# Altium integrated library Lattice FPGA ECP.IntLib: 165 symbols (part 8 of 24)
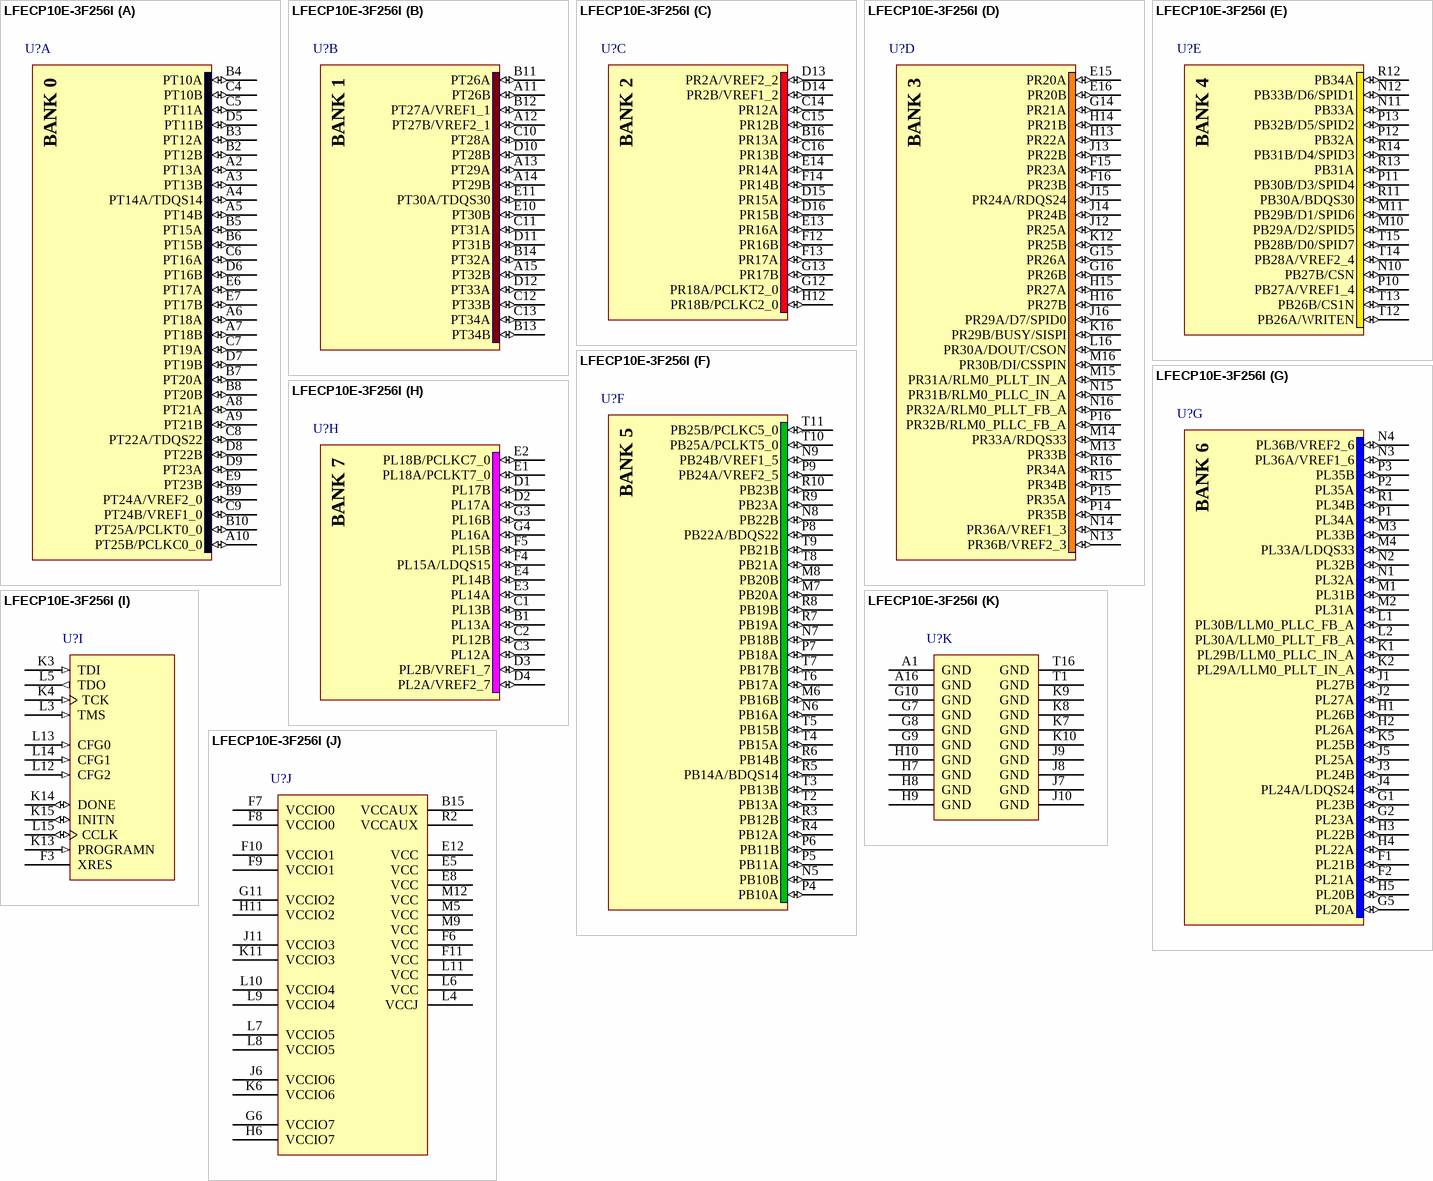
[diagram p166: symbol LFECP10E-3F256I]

## LFECP10E-3F256I
designator U?
ECP 1.2V FPGA, 192 I/Os, 4 PLLs, 10.2K LUTs, 5 sysDSP Blocks, 20 18x18 Multipliers, 256-Pin fpBGA, Speed Grade 3, Industrial Temperature Grade
footprint fpBGA256 (BGA, 256-Leads, Body 17x17mm, Pitch 1mm)
3D model ECP10E-fpBGA256 (256-Ball Fine Pitch Ball Grid Array (fpBGA256))
part A pins: A2 PT13A (io), A3 PT13B (io), A4 PT14A/TDQS14 (io), A5 PT14B (io), A6 PT18A (io), A7 PT18B (io), A8 PT21A (io), A9 PT21B (io), A10 PT25B/PCLKC0_0 (io), B2 PT12B (io), B3 PT12A (io), B4 PT10A (io), B5 PT15A (io), B6 PT15B (io), B7 PT20A (io), B8 PT20B (io), B9 PT24A/VREF2_0 (io), B10 PT25A/PCLKT0_0 (io), C4 PT10B (io), C5 PT11A (io), C6 PT16A (io), C7 PT19A (io), C8 PT22A/TDQS22 (io), C9 PT24B/VREF1_0 (io), D5 PT11B (io), D6 PT16B (io), D7 PT19B (io), D8 PT22B (io), D9 PT23A (io), E6 PT17A (io), E7 PT17B (io), E9 PT23B (io)
part B pins: A11 PT26B (io), A12 PT27B/VREF2_1 (io), A13 PT29A (io), A14 PT29B (io), A15 PT32B (io), B11 PT26A (io), B12 PT27A/VREF1_1 (io), B13 PT34B (io), B14 PT32A (io), C10 PT28A (io), C11 PT31A (io), C12 PT33B (io), C13 PT34A (io), D10 PT28B (io), D11 PT31B (io), D12 PT33A (io), E10 PT30B (io), E11 PT30A/TDQS30 (io)
part C pins: B16 PR13A (io), C14 PR12A (io), C15 PR12B (io), C16 PR13B (io), D13 PR2A/VREF2_2 (io), D14 PR2B/VREF1_2 (io), D15 PR15A (io), D16 PR15B (io), E13 PR16A (io), E14 PR14A (io), F12 PR16B (io), F13 PR17A (io), F14 PR14B (io), G12 PR18A/PCLKT2_0 (io), G13 PR17B (io), H12 PR18B/PCLKC2_0 (io)
part D pins: E15 PR20A (io), E16 PR20B (io), F15 PR23A (io), F16 PR23B (io), G14 PR21A (io), G15 PR26A (io), G16 PR26B (io), H13 PR22A (io), H14 PR21B (io), H15 PR27A (io), H16 PR27B (io), J12 PR25A (io), J13 PR22B (io), J14 PR24B (io), J15 PR24A/RDQS24 (io), J16 PR29A/D7/SPID0 (io), K12 PR25B (io), K16 PR29B/BUSY/SISPI (io), L16 PR30A/DOUT/CSON (io), M13 PR33B (io), M14 PR33A/RDQS33 (io), M15 PR31A/RLM0_PLLT_IN_A (io), M16 PR30B/DI/CSSPIN (io), N13 PR36B/VREF2_3 (io), N14 PR36A/VREF1_3 (io), N15 PR31B/RLM0_PLLC_IN_A (io), N16 PR32A/RLM0_PLLT_FB_A (io), P14 PR35B (io), P15 PR35A (io), P16 PR32B/RLM0_PLLC_FB_A (io), R15 PR34B (io), R16 PR34A (io)
part E pins: M10 PB29A/D2/SPID5 (io), M11 PB29B/D1/SPID6 (io), N10 PB27B/CSN (io), N11 PB33A (io), N12 PB33B/D6/SPID1 (io), P10 PB27A/VREF1_4 (io), P11 PB30B/D3/SPID4 (io), P12 PB32A (io), P13 PB32B/D5/SPID2 (io), R11 PB30A/BDQS30 (io), R12 PB34A (io), R13 PB31A (io), R14 PB31B/D4/SPID3 (io), T12 PB26A/WRITEN (io), T13 PB26B/CS1N (io), T14 PB28A/VREF2_4 (io), T15 PB28B/D0/SPID7 (io)
part F pins: M6 PB16B (io), M7 PB20A (io), M8 PB20B (io), N5 PB10B (io), N6 PB16A (io), N7 PB18B (io), N8 PB22B (io), N9 PB24B/VREF1_5 (io), P4 PB10A (io), P5 PB11A (io), P6 PB11B (io), P7 PB18A (io), P8 PB22A/BDQS22 (io), P9 PB24A/VREF2_5 (io), R3 PB12B (io), R4 PB12A (io), R5 PB14A/BDQS14 (io), R6 PB14B (io), R7 PB19A (io), R8 PB19B (io), R9 PB23A (io), R10 PB23B (io), T2 PB13A (io), T3 PB13B (io), T4 PB15A (io), T5 PB15B (io), T6 PB17A (io), T7 PB17B (io), T8 PB21A (io), T9 PB21B (io), T10 PB25A/PCLKT5_0 (io), T11 PB25B/PCLKC5_0 (io)
part G pins: F1 PL21B (io), F2 PL21A (io), G1 PL23B (io), G2 PL23A (io), G5 PL20A (io), H1 PL26B (io), H2 PL26A (io), H3 PL22B (io), H4 PL22A (io), H5 PL20B (io), J1 PL27B (io), J2 PL27A (io), J3 PL24B (io), J4 PL24A/LDQS24 (io), J5 PL25A (io), K1 PL29B/LLM0_PLLC_IN_A (io), K2 PL29A/LLM0_PLLT_IN_A (io), K5 PL25B (io), L1 PL30B/LLM0_PLLC_FB_A (io), L2 PL30A/LLM0_PLLT_FB_A (io), M1 PL31B (io), M2 PL31A (io), M3 PL33B (io), M4 PL33A/LDQS33 (io), N1 PL32A (io), N2 PL32B (io), N3 PL36A/VREF1_6 (io), N4 PL36B/VREF2_6 (io), P1 PL34A (io), P2 PL35A (io), P3 PL35B (io), R1 PL34B (io)
part H pins: B1 PL13A (io), C1 PL13B (io), C2 PL12B (io), C3 PL12A (io), D1 PL17B (io), D2 PL17A (io), D3 PL2B/VREF1_7 (io), D4 PL2A/VREF2_7 (io), E1 PL18A/PCLKT7_0 (io), E2 PL18B/PCLKC7_0 (io), E3 PL14A (io), E4 PL14B (io), F4 PL15A/LDQS15 (io), F5 PL15B (io), G3 PL16B (io), G4 PL16A (io)
part I pins: F3 XRES, K3 TDI (in), K4 TCK (in), K13 PROGRAMN (in), K14 DONE (io), K15 INITN (io), L3 TMS (in), L5 TDO (out), L12 CFG2 (in), L13 CFG0 (in), L14 CFG1 (in), L15 CCLK (io)
part J pins: B15 VCCAUX (power), E5 VCC (power), E8 VCC (power), E12 VCC (power), F6 VCC (power), F7 VCCIO0 (power), F8 VCCIO0 (power), F9 VCCIO1 (power), F10 VCCIO1 (power), F11 VCC (power), G6 VCCIO7 (power), G11 VCCIO2 (power), H6 VCCIO7 (power), H11 VCCIO2 (power), J6 VCCIO6 (power), J11 VCCIO3 (power), K6 VCCIO6 (power), K11 VCCIO3 (power), L4 VCCJ (power), L6 VCC (power), L7 VCCIO5 (power), L8 VCCIO5 (power), L9 VCCIO4 (power), L10 VCCIO4 (power), L11 VCC (power), M5 VCC (power), M9 VCC (power), M12 VCC (power), R2 VCCAUX (power)
part K pins: A1 GND (power), A16 GND (power), G7 GND (power), G8 GND (power), G9 GND (power), G10 GND (power), H7 GND (power), H8 GND (power), H9 GND (power), H10 GND (power), J7 GND (power), J8 GND (power), J9 GND (power), J10 GND (power), K7 GND (power), K8 GND (power), K9 GND (power), K10 GND (power), T1 GND (power), T16 GND (power)

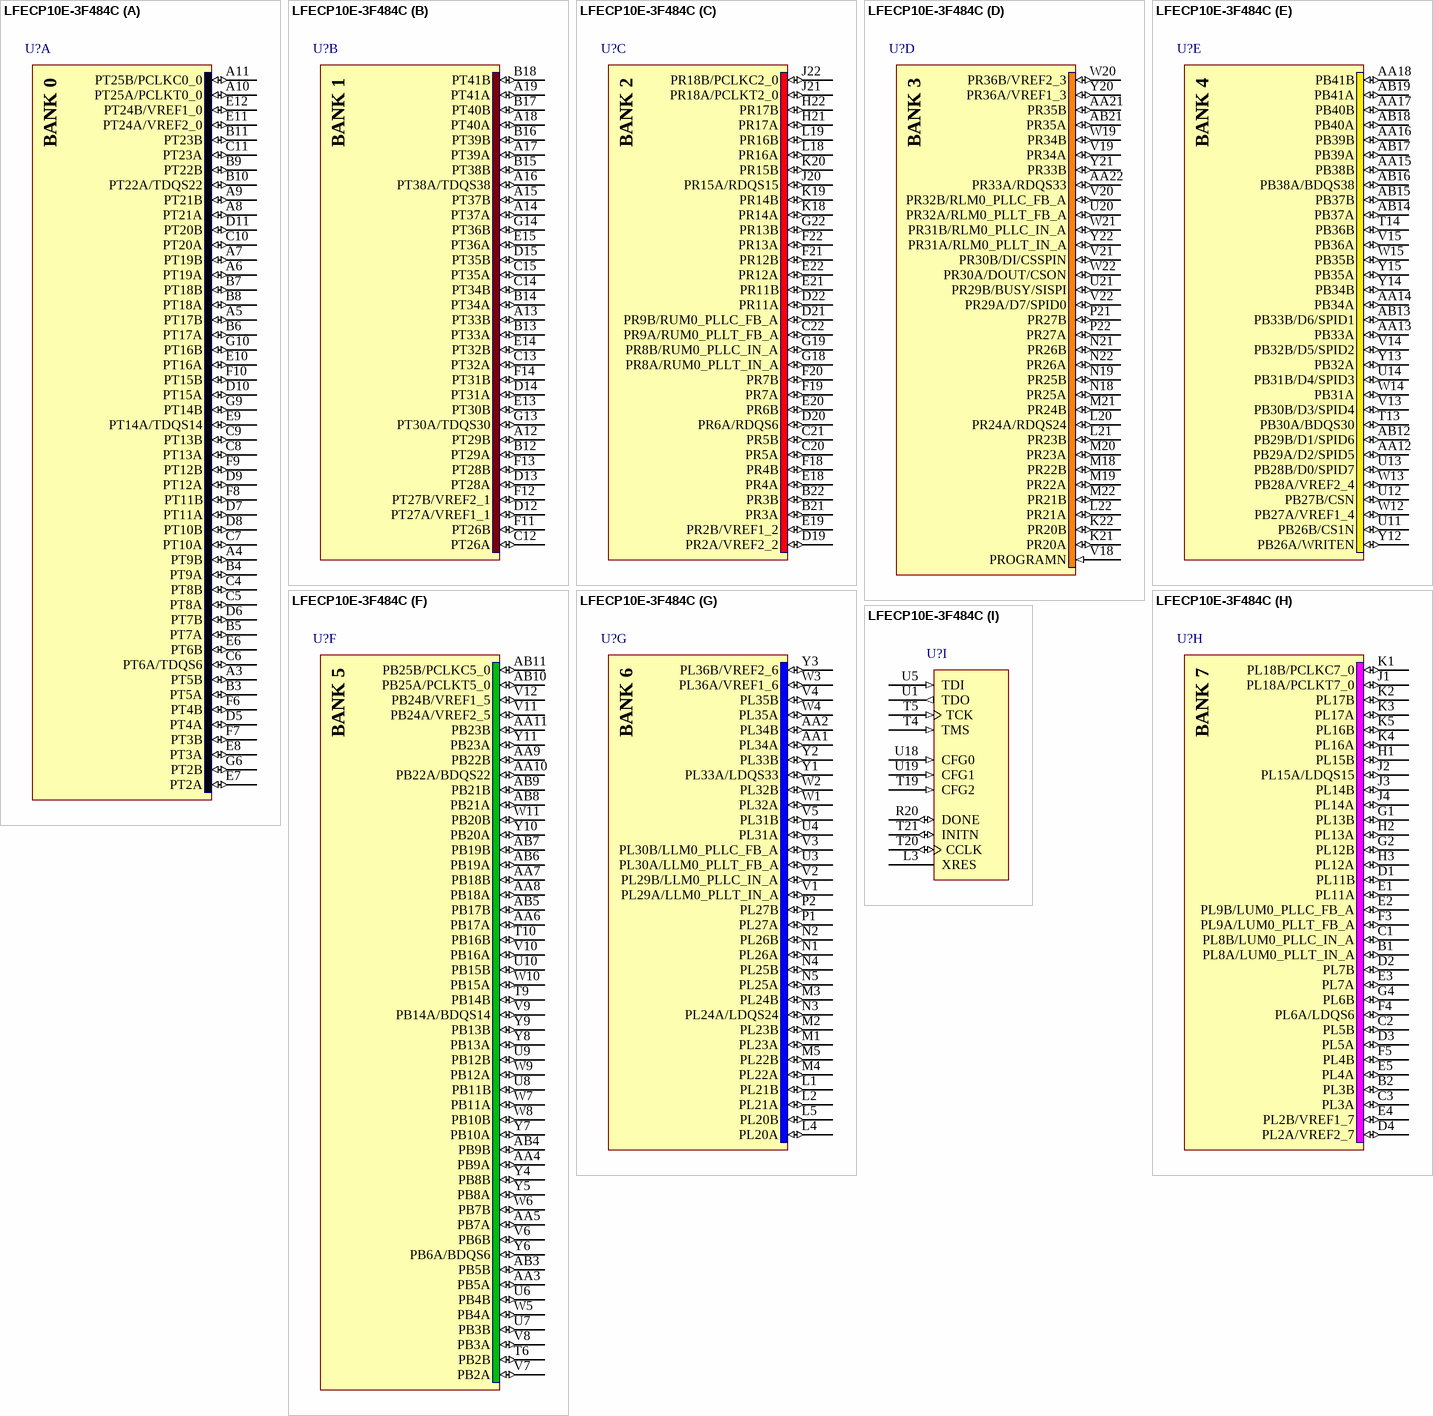
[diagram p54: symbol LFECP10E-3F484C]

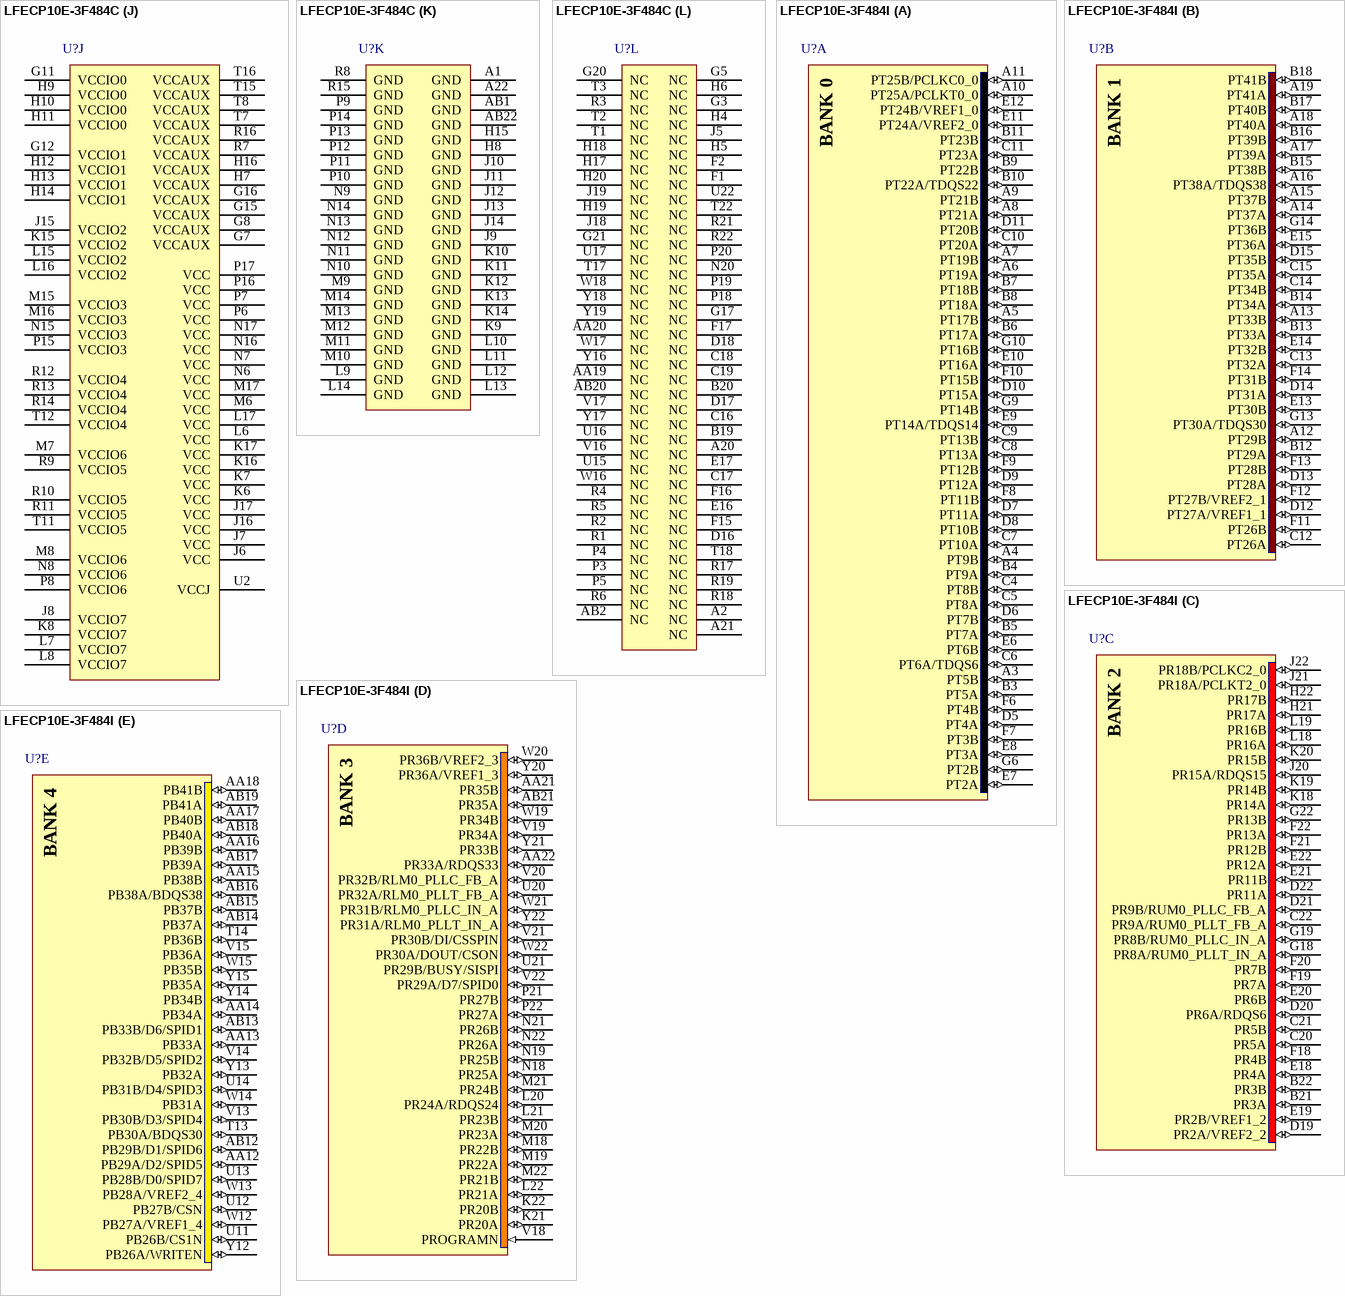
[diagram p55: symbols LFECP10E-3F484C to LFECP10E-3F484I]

## LFECP10E-3F484C
designator U?
ECP 1.2V FPGA, 288 I/Os, 4 PLLs, 10.2K LUTs, 5 sysDSP Blocks, 20 18x18 Multipliers, 484-Pin fpBGA, Speed Grade 3, Commercial Temperature Grade
footprint fpBGA484 (BGA, 484-Leads, Body 23x23mm, Pitch 1mm)
3D model ECP10E-fpBGA484 (484-Ball Fine Pitch Ball Grid Array (fpBGA484))
part A pins: A3 PT5B (io), A4 PT9B (io), A5 PT17B (io), A6 PT19A (io), A7 PT19B (io), A8 PT21A (io), A9 PT21B (io), A10 PT25A/PCLKT0_0 (io), A11 PT25B/PCLKC0_0 (io), B3 PT5A (io), B4 PT9A (io), B5 PT7A (io), B6 PT17A (io), B7 PT18B (io), B8 PT18A (io), B9 PT22B (io), B10 PT22A/TDQS22 (io), B11 PT23B (io), C4 PT8B (io), C5 PT8A (io), C6 PT6A/TDQS6 (io), C7 PT10A (io), C8 PT13A (io), C9 PT13B (io), C10 PT20A (io), C11 PT23A (io), D5 PT4A (io), D6 PT7B (io), D7 PT11A (io), D8 PT10B (io), D9 PT12A (io), D10 PT15A (io), D11 PT20B (io), E6 PT6B (io), E7 PT2A (io), E8 PT3A (io), E9 PT14A/TDQS14 (io), E10 PT16A (io), E11 PT24A/VREF2_0 (io), E12 PT24B/VREF1_0 (io), F6 PT4B (io), F7 PT3B (io), F8 PT11B (io), F9 PT12B (io), F10 PT15B (io), G6 PT2B (io), G9 PT14B (io), G10 PT16B (io)
part B pins: A12 PT29B (io), A13 PT33B (io), A14 PT37A (io), A15 PT37B (io), A16 PT38A/TDQS38 (io), A17 PT39A (io), A18 PT40A (io), A19 PT41A (io), B12 PT29A (io), B13 PT33A (io), B14 PT34A (io), B15 PT38B (io), B16 PT39B (io), B17 PT40B (io), B18 PT41B (io), C12 PT26A (io), C13 PT32A (io), C14 PT34B (io), C15 PT35A (io), D12 PT27A/VREF1_1 (io), D13 PT28A (io), D14 PT31A (io), D15 PT35B (io), E13 PT30B (io), E14 PT32B (io), E15 PT36A (io), F11 PT26B (io), F12 PT27B/VREF2_1 (io), F13 PT28B (io), F14 PT31B (io), G13 PT30A/TDQS30 (io), G14 PT36B (io)
part C pins: B21 PR3A (io), B22 PR3B (io), C20 PR5A (io), C21 PR5B (io), C22 PR9A/RUM0_PLLT_FB_A (io), D19 PR2A/VREF2_2 (io), D20 PR6A/RDQS6 (io), D21 PR9B/RUM0_PLLC_FB_A (io), D22 PR11A (io), E18 PR4A (io), E19 PR2B/VREF1_2 (io), E20 PR6B (io), E21 PR11B (io), E22 PR12A (io), F18 PR4B (io), F19 PR7A (io), F20 PR7B (io), F21 PR12B (io), F22 PR13A (io), G18 PR8A/RUM0_PLLT_IN_A (io), G19 PR8B/RUM0_PLLC_IN_A (io), G22 PR13B (io), H21 PR17A (io), H22 PR17B (io), J20 PR15A/RDQS15 (io), J21 PR18A/PCLKT2_0 (io), J22 PR18B/PCLKC2_0 (io), K18 PR14A (io), K19 PR14B (io), K20 PR15B (io), L18 PR16A (io), L19 PR16B (io)
part D pins: AA21 PR35B (io), AA22 PR33A/RDQS33 (io), AB21 PR35A (io), K21 PR20A (io), K22 PR20B (io), L20 PR24A/RDQS24 (io), L21 PR23B (io), L22 PR21A (io), M18 PR22B (io), M19 PR22A (io), M20 PR23A (io), M21 PR24B (io), M22 PR21B (io), N18 PR25A (io), N19 PR25B (io), N21 PR26B (io), N22 PR26A (io), P21 PR27B (io), P22 PR27A (io), U20 PR32A/RLM0_PLLT_FB_A (io), U21 PR29B/BUSY/SISPI (io), V18 PROGRAMN (in), V19 PR34A (io), V20 PR32B/RLM0_PLLC_FB_A (io), V21 PR30B/DI/CSSPIN (io), V22 PR29A/D7/SPID0 (io), W19 PR34B (io), W20 PR36B/VREF2_3 (io), W21 PR31B/RLM0_PLLC_IN_A (io), W22 PR30A/DOUT/CSON (io), Y20 PR36A/VREF1_3 (io), Y21 PR33B (io), Y22 PR31A/RLM0_PLLT_IN_A (io)
part E pins: AA12 PB29A/D2/SPID5 (io), AA13 PB33A (io), AA14 PB34A (io), AA15 PB38B (io), AA16 PB39B (io), AA17 PB40B (io), AA18 PB41B (io), AB12 PB29B/D1/SPID6 (io), AB13 PB33B/D6/SPID1 (io), AB14 PB37A (io), AB15 PB37B (io), AB16 PB38A/BDQS38 (io), AB17 PB39A (io), AB18 PB40A (io), AB19 PB41A (io), T13 PB30A/BDQS30 (io), T14 PB36B (io), U11 PB26B/CS1N (io), U12 PB27B/CSN (io), U13 PB28B/D0/SPID7 (io), U14 PB31B/D4/SPID3 (io), V13 PB30B/D3/SPID4 (io), V14 PB32B/D5/SPID2 (io), V15 PB36A (io), W12 PB27A/VREF1_4 (io), W13 PB28A/VREF2_4 (io), W14 PB31A (io), W15 PB35B (io), Y12 PB26A/WRITEN (io), Y13 PB32A (io), Y14 PB34B (io), Y15 PB35A (io)
part F pins: AA3 PB5A (io), AA4 PB9A (io), AA5 PB7A (io), AA6 PB17A (io), AA7 PB18B (io), AA8 PB18A (io), AA9 PB22B (io), AA10 PB22A/BDQS22 (io), AA11 PB23B (io), AB3 PB5B (io), AB4 PB9B (io), AB5 PB17B (io), AB6 PB19A (io), AB7 PB19B (io), AB8 PB21A (io), AB9 PB21B (io), AB10 PB25A/PCLKT5_0 (io), AB11 PB25B/PCLKC5_0 (io), T6 PB2B (io), T9 PB14B (io), T10 PB16B (io), U6 PB4B (io), U7 PB3B (io), U8 PB11B (io), U9 PB12B (io), U10 PB15B (io), V6 PB6B (io), V7 PB2A (io), V8 PB3A (io), V9 PB14A/BDQS14 (io), V10 PB16A (io), V11 PB24A/VREF2_5 (io), V12 PB24B/VREF1_5 (io), W5 PB4A (io), W6 PB7B (io), W7 PB11A (io), W8 PB10B (io), W9 PB12A (io), W10 PB15A (io), W11 PB20B (io), Y4 PB8B (io), Y5 PB8A (io), Y6 PB6A/BDQS6 (io), Y7 PB10A (io), Y8 PB13A (io), Y9 PB13B (io), Y10 PB20A (io), Y11 PB23A (io)
part G pins: AA1 PL34A (io), AA2 PL34B (io), L1 PL21B (io), L2 PL21A (io), L4 PL20A (io), L5 PL20B (io), M1 PL23A (io), M2 PL23B (io), M3 PL24B (io), M4 PL22A (io), M5 PL22B (io), N1 PL26A (io), N2 PL26B (io), N3 PL24A/LDQS24 (io), N4 PL25B (io), N5 PL25A (io), P1 PL27A (io), P2 PL27B (io), U3 PL30A/LLM0_PLLT_FB_A (io), U4 PL31A (io), V1 PL29A/LLM0_PLLT_IN_A (io), V2 PL29B/LLM0_PLLC_IN_A (io), V3 PL30B/LLM0_PLLC_FB_A (io), V4 PL35B (io), V5 PL31B (io), W1 PL32A (io), W2 PL32B (io), W3 PL36A/VREF1_6 (io), W4 PL35A (io), Y1 PL33A/LDQS33 (io), Y2 PL33B (io), Y3 PL36B/VREF2_6 (io)
part H pins: B1 PL8A/LUM0_PLLT_IN_A (io), B2 PL3B (io), C1 PL8B/LUM0_PLLC_IN_A (io), C2 PL5B (io), C3 PL3A (io), D1 PL11B (io), D2 PL7B (io), D3 PL5A (io), D4 PL2A/VREF2_7 (io), E1 PL11A (io), E2 PL9B/LUM0_PLLC_FB_A (io), E3 PL7A (io), E4 PL2B/VREF1_7 (io), E5 PL4A (io), F3 PL9A/LUM0_PLLT_FB_A (io), F4 PL6A/LDQS6 (io), F5 PL4B (io), G1 PL13B (io), G2 PL12B (io), G4 PL6B (io), H1 PL15B (io), H2 PL13A (io), H3 PL12A (io), J1 PL18A/PCLKT7_0 (io), J2 PL15A/LDQS15 (io), J3 PL14B (io), J4 PL14A (io), K1 PL18B/PCLKC7_0 (io), K2 PL17B (io), K3 PL17A (io), K4 PL16A (io), K5 PL16B (io)
part I pins: L3 XRES, R20 DONE (io), T4 TMS (in), T5 TCK (in), T19 CFG2 (in), T20 CCLK (io), T21 INITN (io), U1 TDO (out), U5 TDI (in), U18 CFG0 (in), U19 CFG1 (in)
part J pins: G7 VCCAUX (power), G8 VCCAUX (power), G11 VCCIO0 (power), G12 VCCIO1 (power), G15 VCCAUX (power), G16 VCCAUX (power), H7 VCCAUX (power), H9 VCCIO0 (power), H10 VCCIO0 (power), H11 VCCIO0 (power), H12 VCCIO1 (power), H13 VCCIO1 (power), H14 VCCIO1 (power), H16 VCCAUX (power), J6 VCC (power), J7 VCC (power), J8 VCCIO7 (power), J15 VCCIO2 (power), J16 VCC (power), J17 VCC (power), K6 VCC (power), K7 VCC (power), K8 VCCIO7 (power), K15 VCCIO2 (power), K16 VCC (power), K17 VCC (power), L6 VCC (power), L7 VCCIO7 (power), L8 VCCIO7 (power), L15 VCCIO2 (power), L16 VCCIO2 (power), L17 VCC (power), M6 VCC (power), M7 VCCIO6 (power), M8 VCCIO6 (power), M15 VCCIO3 (power), M16 VCCIO3 (power), M17 VCC (power), N6 VCC (power), N7 VCC (power), N8 VCCIO6 (power), N15 VCCIO3 (power), N16 VCC (power), N17 VCC (power), P6 VCC (power), P7 VCC (power), P8 VCCIO6 (power), P15 VCCIO3 (power), P16 VCC (power), P17 VCC (power), R7 VCCAUX (power), R9 VCCIO5 (power), R10 VCCIO5 (power), R11 VCCIO5 (power), R12 VCCIO4 (power), R13 VCCIO4 (power), R14 VCCIO4 (power), R16 VCCAUX (power), T7 VCCAUX (power), T8 VCCAUX (power), T11 VCCIO5 (power), T12 VCCIO4 (power), T15 VCCAUX (power), T16 VCCAUX (power), U2 VCCJ (power)
part K pins: A1 GND (power), A22 GND (power), AB1 GND (power), AB22 GND (power), H8 GND (power), H15 GND (power), J9 GND (power), J10 GND (power), J11 GND (power), J12 GND (power), J13 GND (power), J14 GND (power), K9 GND (power), K10 GND (power), K11 GND (power), K12 GND (power), K13 GND (power), K14 GND (power), L9 GND (power), L10 GND (power), L11 GND (power), L12 GND (power), L13 GND (power), L14 GND (power), M9 GND (power), M10 GND (power), M11 GND (power), M12 GND (power), M13 GND (power), M14 GND (power), N9 GND (power), N10 GND (power), N11 GND (power), N12 GND (power), N13 GND (power), N14 GND (power), P9 GND (power), P10 GND (power), P11 GND (power), P12 GND (power), P13 GND (power), P14 GND (power), R8 GND (power), R15 GND (power)
part L pins: A2 NC, A20 NC, A21 NC, AA19 NC, AA20 NC, AB2 NC, AB20 NC, B19 NC, B20 NC, C16 NC, C17 NC, C18 NC, C19 NC, D16 NC, D17 NC, D18 NC, E16 NC, E17 NC, F1 NC, F2 NC, F15 NC, F16 NC, F17 NC, G3 NC, G5 NC, G17 NC, G20 NC, G21 NC, H4 NC, H5 NC, H6 NC, H17 NC, H18 NC, H19 NC, H20 NC, J5 NC, J18 NC, J19 NC, N20 NC, P3 NC, P4 NC, P5 NC, P18 NC, P19 NC, P20 NC, R1 NC, R2 NC, R3 NC, R4 NC, R5 NC, R6 NC, R17 NC, R18 NC, R19 NC, R21 NC, R22 NC, T1 NC, T2 NC, T3 NC, T17 NC, T18 NC, T22 NC, U15 NC, U16 NC, U17 NC, U22 NC, V16 NC, V17 NC, W16 NC, W17 NC, W18 NC, Y16 NC, Y17 NC, Y18 NC, Y19 NC

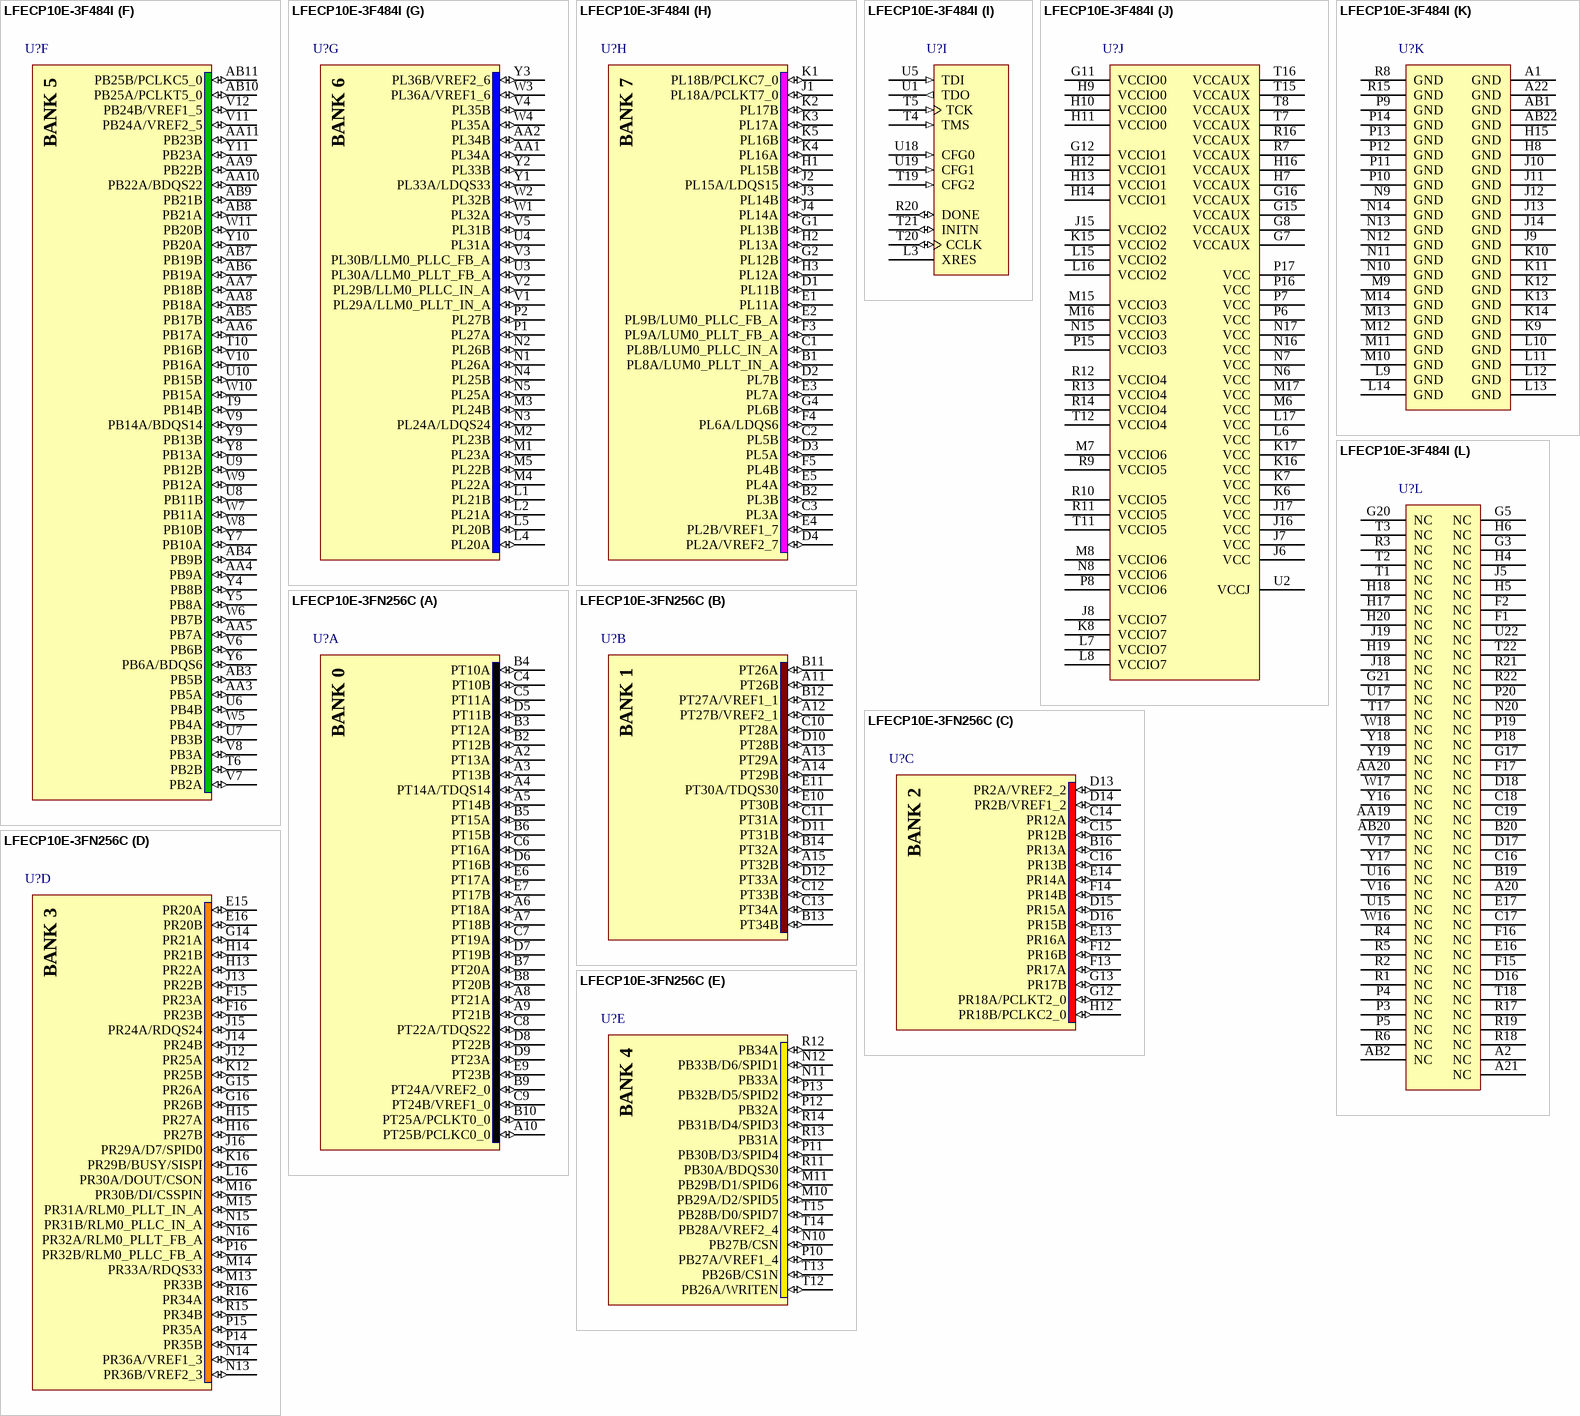
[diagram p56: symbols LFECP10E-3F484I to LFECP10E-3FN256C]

## LFECP10E-3F484I
designator U?
ECP 1.2V FPGA, 288 I/Os, 4 PLLs, 10.2K LUTs, 5 sysDSP Blocks, 20 18x18 Multipliers, 484-Pin fpBGA, Speed Grade 3, Industrial Temperature Grade
footprint fpBGA484 (BGA, 484-Leads, Body 23x23mm, Pitch 1mm)
3D model ECP10E-fpBGA484 (484-Ball Fine Pitch Ball Grid Array (fpBGA484))
part A pins: A3 PT5B (io), A4 PT9B (io), A5 PT17B (io), A6 PT19A (io), A7 PT19B (io), A8 PT21A (io), A9 PT21B (io), A10 PT25A/PCLKT0_0 (io), A11 PT25B/PCLKC0_0 (io), B3 PT5A (io), B4 PT9A (io), B5 PT7A (io), B6 PT17A (io), B7 PT18B (io), B8 PT18A (io), B9 PT22B (io), B10 PT22A/TDQS22 (io), B11 PT23B (io), C4 PT8B (io), C5 PT8A (io), C6 PT6A/TDQS6 (io), C7 PT10A (io), C8 PT13A (io), C9 PT13B (io), C10 PT20A (io), C11 PT23A (io), D5 PT4A (io), D6 PT7B (io), D7 PT11A (io), D8 PT10B (io), D9 PT12A (io), D10 PT15A (io), D11 PT20B (io), E6 PT6B (io), E7 PT2A (io), E8 PT3A (io), E9 PT14A/TDQS14 (io), E10 PT16A (io), E11 PT24A/VREF2_0 (io), E12 PT24B/VREF1_0 (io), F6 PT4B (io), F7 PT3B (io), F8 PT11B (io), F9 PT12B (io), F10 PT15B (io), G6 PT2B (io), G9 PT14B (io), G10 PT16B (io)
part B pins: A12 PT29B (io), A13 PT33B (io), A14 PT37A (io), A15 PT37B (io), A16 PT38A/TDQS38 (io), A17 PT39A (io), A18 PT40A (io), A19 PT41A (io), B12 PT29A (io), B13 PT33A (io), B14 PT34A (io), B15 PT38B (io), B16 PT39B (io), B17 PT40B (io), B18 PT41B (io), C12 PT26A (io), C13 PT32A (io), C14 PT34B (io), C15 PT35A (io), D12 PT27A/VREF1_1 (io), D13 PT28A (io), D14 PT31A (io), D15 PT35B (io), E13 PT30B (io), E14 PT32B (io), E15 PT36A (io), F11 PT26B (io), F12 PT27B/VREF2_1 (io), F13 PT28B (io), F14 PT31B (io), G13 PT30A/TDQS30 (io), G14 PT36B (io)
part C pins: B21 PR3A (io), B22 PR3B (io), C20 PR5A (io), C21 PR5B (io), C22 PR9A/RUM0_PLLT_FB_A (io), D19 PR2A/VREF2_2 (io), D20 PR6A/RDQS6 (io), D21 PR9B/RUM0_PLLC_FB_A (io), D22 PR11A (io), E18 PR4A (io), E19 PR2B/VREF1_2 (io), E20 PR6B (io), E21 PR11B (io), E22 PR12A (io), F18 PR4B (io), F19 PR7A (io), F20 PR7B (io), F21 PR12B (io), F22 PR13A (io), G18 PR8A/RUM0_PLLT_IN_A (io), G19 PR8B/RUM0_PLLC_IN_A (io), G22 PR13B (io), H21 PR17A (io), H22 PR17B (io), J20 PR15A/RDQS15 (io), J21 PR18A/PCLKT2_0 (io), J22 PR18B/PCLKC2_0 (io), K18 PR14A (io), K19 PR14B (io), K20 PR15B (io), L18 PR16A (io), L19 PR16B (io)
part D pins: AA21 PR35B (io), AA22 PR33A/RDQS33 (io), AB21 PR35A (io), K21 PR20A (io), K22 PR20B (io), L20 PR24A/RDQS24 (io), L21 PR23B (io), L22 PR21A (io), M18 PR22B (io), M19 PR22A (io), M20 PR23A (io), M21 PR24B (io), M22 PR21B (io), N18 PR25A (io), N19 PR25B (io), N21 PR26B (io), N22 PR26A (io), P21 PR27B (io), P22 PR27A (io), U20 PR32A/RLM0_PLLT_FB_A (io), U21 PR29B/BUSY/SISPI (io), V18 PROGRAMN (in), V19 PR34A (io), V20 PR32B/RLM0_PLLC_FB_A (io), V21 PR30B/DI/CSSPIN (io), V22 PR29A/D7/SPID0 (io), W19 PR34B (io), W20 PR36B/VREF2_3 (io), W21 PR31B/RLM0_PLLC_IN_A (io), W22 PR30A/DOUT/CSON (io), Y20 PR36A/VREF1_3 (io), Y21 PR33B (io), Y22 PR31A/RLM0_PLLT_IN_A (io)
part E pins: AA12 PB29A/D2/SPID5 (io), AA13 PB33A (io), AA14 PB34A (io), AA15 PB38B (io), AA16 PB39B (io), AA17 PB40B (io), AA18 PB41B (io), AB12 PB29B/D1/SPID6 (io), AB13 PB33B/D6/SPID1 (io), AB14 PB37A (io), AB15 PB37B (io), AB16 PB38A/BDQS38 (io), AB17 PB39A (io), AB18 PB40A (io), AB19 PB41A (io), T13 PB30A/BDQS30 (io), T14 PB36B (io), U11 PB26B/CS1N (io), U12 PB27B/CSN (io), U13 PB28B/D0/SPID7 (io), U14 PB31B/D4/SPID3 (io), V13 PB30B/D3/SPID4 (io), V14 PB32B/D5/SPID2 (io), V15 PB36A (io), W12 PB27A/VREF1_4 (io), W13 PB28A/VREF2_4 (io), W14 PB31A (io), W15 PB35B (io), Y12 PB26A/WRITEN (io), Y13 PB32A (io), Y14 PB34B (io), Y15 PB35A (io)
part F pins: AA3 PB5A (io), AA4 PB9A (io), AA5 PB7A (io), AA6 PB17A (io), AA7 PB18B (io), AA8 PB18A (io), AA9 PB22B (io), AA10 PB22A/BDQS22 (io), AA11 PB23B (io), AB3 PB5B (io), AB4 PB9B (io), AB5 PB17B (io), AB6 PB19A (io), AB7 PB19B (io), AB8 PB21A (io), AB9 PB21B (io), AB10 PB25A/PCLKT5_0 (io), AB11 PB25B/PCLKC5_0 (io), T6 PB2B (io), T9 PB14B (io), T10 PB16B (io), U6 PB4B (io), U7 PB3B (io), U8 PB11B (io), U9 PB12B (io), U10 PB15B (io), V6 PB6B (io), V7 PB2A (io), V8 PB3A (io), V9 PB14A/BDQS14 (io), V10 PB16A (io), V11 PB24A/VREF2_5 (io), V12 PB24B/VREF1_5 (io), W5 PB4A (io), W6 PB7B (io), W7 PB11A (io), W8 PB10B (io), W9 PB12A (io), W10 PB15A (io), W11 PB20B (io), Y4 PB8B (io), Y5 PB8A (io), Y6 PB6A/BDQS6 (io), Y7 PB10A (io), Y8 PB13A (io), Y9 PB13B (io), Y10 PB20A (io), Y11 PB23A (io)
part G pins: AA1 PL34A (io), AA2 PL34B (io), L1 PL21B (io), L2 PL21A (io), L4 PL20A (io), L5 PL20B (io), M1 PL23A (io), M2 PL23B (io), M3 PL24B (io), M4 PL22A (io), M5 PL22B (io), N1 PL26A (io), N2 PL26B (io), N3 PL24A/LDQS24 (io), N4 PL25B (io), N5 PL25A (io), P1 PL27A (io), P2 PL27B (io), U3 PL30A/LLM0_PLLT_FB_A (io), U4 PL31A (io), V1 PL29A/LLM0_PLLT_IN_A (io), V2 PL29B/LLM0_PLLC_IN_A (io), V3 PL30B/LLM0_PLLC_FB_A (io), V4 PL35B (io), V5 PL31B (io), W1 PL32A (io), W2 PL32B (io), W3 PL36A/VREF1_6 (io), W4 PL35A (io), Y1 PL33A/LDQS33 (io), Y2 PL33B (io), Y3 PL36B/VREF2_6 (io)
part H pins: B1 PL8A/LUM0_PLLT_IN_A (io), B2 PL3B (io), C1 PL8B/LUM0_PLLC_IN_A (io), C2 PL5B (io), C3 PL3A (io), D1 PL11B (io), D2 PL7B (io), D3 PL5A (io), D4 PL2A/VREF2_7 (io), E1 PL11A (io), E2 PL9B/LUM0_PLLC_FB_A (io), E3 PL7A (io), E4 PL2B/VREF1_7 (io), E5 PL4A (io), F3 PL9A/LUM0_PLLT_FB_A (io), F4 PL6A/LDQS6 (io), F5 PL4B (io), G1 PL13B (io), G2 PL12B (io), G4 PL6B (io), H1 PL15B (io), H2 PL13A (io), H3 PL12A (io), J1 PL18A/PCLKT7_0 (io), J2 PL15A/LDQS15 (io), J3 PL14B (io), J4 PL14A (io), K1 PL18B/PCLKC7_0 (io), K2 PL17B (io), K3 PL17A (io), K4 PL16A (io), K5 PL16B (io)
part I pins: L3 XRES, R20 DONE (io), T4 TMS (in), T5 TCK (in), T19 CFG2 (in), T20 CCLK (io), T21 INITN (io), U1 TDO (out), U5 TDI (in), U18 CFG0 (in), U19 CFG1 (in)
part J pins: G7 VCCAUX (power), G8 VCCAUX (power), G11 VCCIO0 (power), G12 VCCIO1 (power), G15 VCCAUX (power), G16 VCCAUX (power), H7 VCCAUX (power), H9 VCCIO0 (power), H10 VCCIO0 (power), H11 VCCIO0 (power), H12 VCCIO1 (power), H13 VCCIO1 (power), H14 VCCIO1 (power), H16 VCCAUX (power), J6 VCC (power), J7 VCC (power), J8 VCCIO7 (power), J15 VCCIO2 (power), J16 VCC (power), J17 VCC (power), K6 VCC (power), K7 VCC (power), K8 VCCIO7 (power), K15 VCCIO2 (power), K16 VCC (power), K17 VCC (power), L6 VCC (power), L7 VCCIO7 (power), L8 VCCIO7 (power), L15 VCCIO2 (power), L16 VCCIO2 (power), L17 VCC (power), M6 VCC (power), M7 VCCIO6 (power), M8 VCCIO6 (power), M15 VCCIO3 (power), M16 VCCIO3 (power), M17 VCC (power), N6 VCC (power), N7 VCC (power), N8 VCCIO6 (power), N15 VCCIO3 (power), N16 VCC (power), N17 VCC (power), P6 VCC (power), P7 VCC (power), P8 VCCIO6 (power), P15 VCCIO3 (power), P16 VCC (power), P17 VCC (power), R7 VCCAUX (power), R9 VCCIO5 (power), R10 VCCIO5 (power), R11 VCCIO5 (power), R12 VCCIO4 (power), R13 VCCIO4 (power), R14 VCCIO4 (power), R16 VCCAUX (power), T7 VCCAUX (power), T8 VCCAUX (power), T11 VCCIO5 (power), T12 VCCIO4 (power), T15 VCCAUX (power), T16 VCCAUX (power), U2 VCCJ (power)
part K pins: A1 GND (power), A22 GND (power), AB1 GND (power), AB22 GND (power), H8 GND (power), H15 GND (power), J9 GND (power), J10 GND (power), J11 GND (power), J12 GND (power), J13 GND (power), J14 GND (power), K9 GND (power), K10 GND (power), K11 GND (power), K12 GND (power), K13 GND (power), K14 GND (power), L9 GND (power), L10 GND (power), L11 GND (power), L12 GND (power), L13 GND (power), L14 GND (power), M9 GND (power), M10 GND (power), M11 GND (power), M12 GND (power), M13 GND (power), M14 GND (power), N9 GND (power), N10 GND (power), N11 GND (power), N12 GND (power), N13 GND (power), N14 GND (power), P9 GND (power), P10 GND (power), P11 GND (power), P12 GND (power), P13 GND (power), P14 GND (power), R8 GND (power), R15 GND (power)
part L pins: A2 NC, A20 NC, A21 NC, AA19 NC, AA20 NC, AB2 NC, AB20 NC, B19 NC, B20 NC, C16 NC, C17 NC, C18 NC, C19 NC, D16 NC, D17 NC, D18 NC, E16 NC, E17 NC, F1 NC, F2 NC, F15 NC, F16 NC, F17 NC, G3 NC, G5 NC, G17 NC, G20 NC, G21 NC, H4 NC, H5 NC, H6 NC, H17 NC, H18 NC, H19 NC, H20 NC, J5 NC, J18 NC, J19 NC, N20 NC, P3 NC, P4 NC, P5 NC, P18 NC, P19 NC, P20 NC, R1 NC, R2 NC, R3 NC, R4 NC, R5 NC, R6 NC, R17 NC, R18 NC, R19 NC, R21 NC, R22 NC, T1 NC, T2 NC, T3 NC, T17 NC, T18 NC, T22 NC, U15 NC, U16 NC, U17 NC, U22 NC, V16 NC, V17 NC, W16 NC, W17 NC, W18 NC, Y16 NC, Y17 NC, Y18 NC, Y19 NC

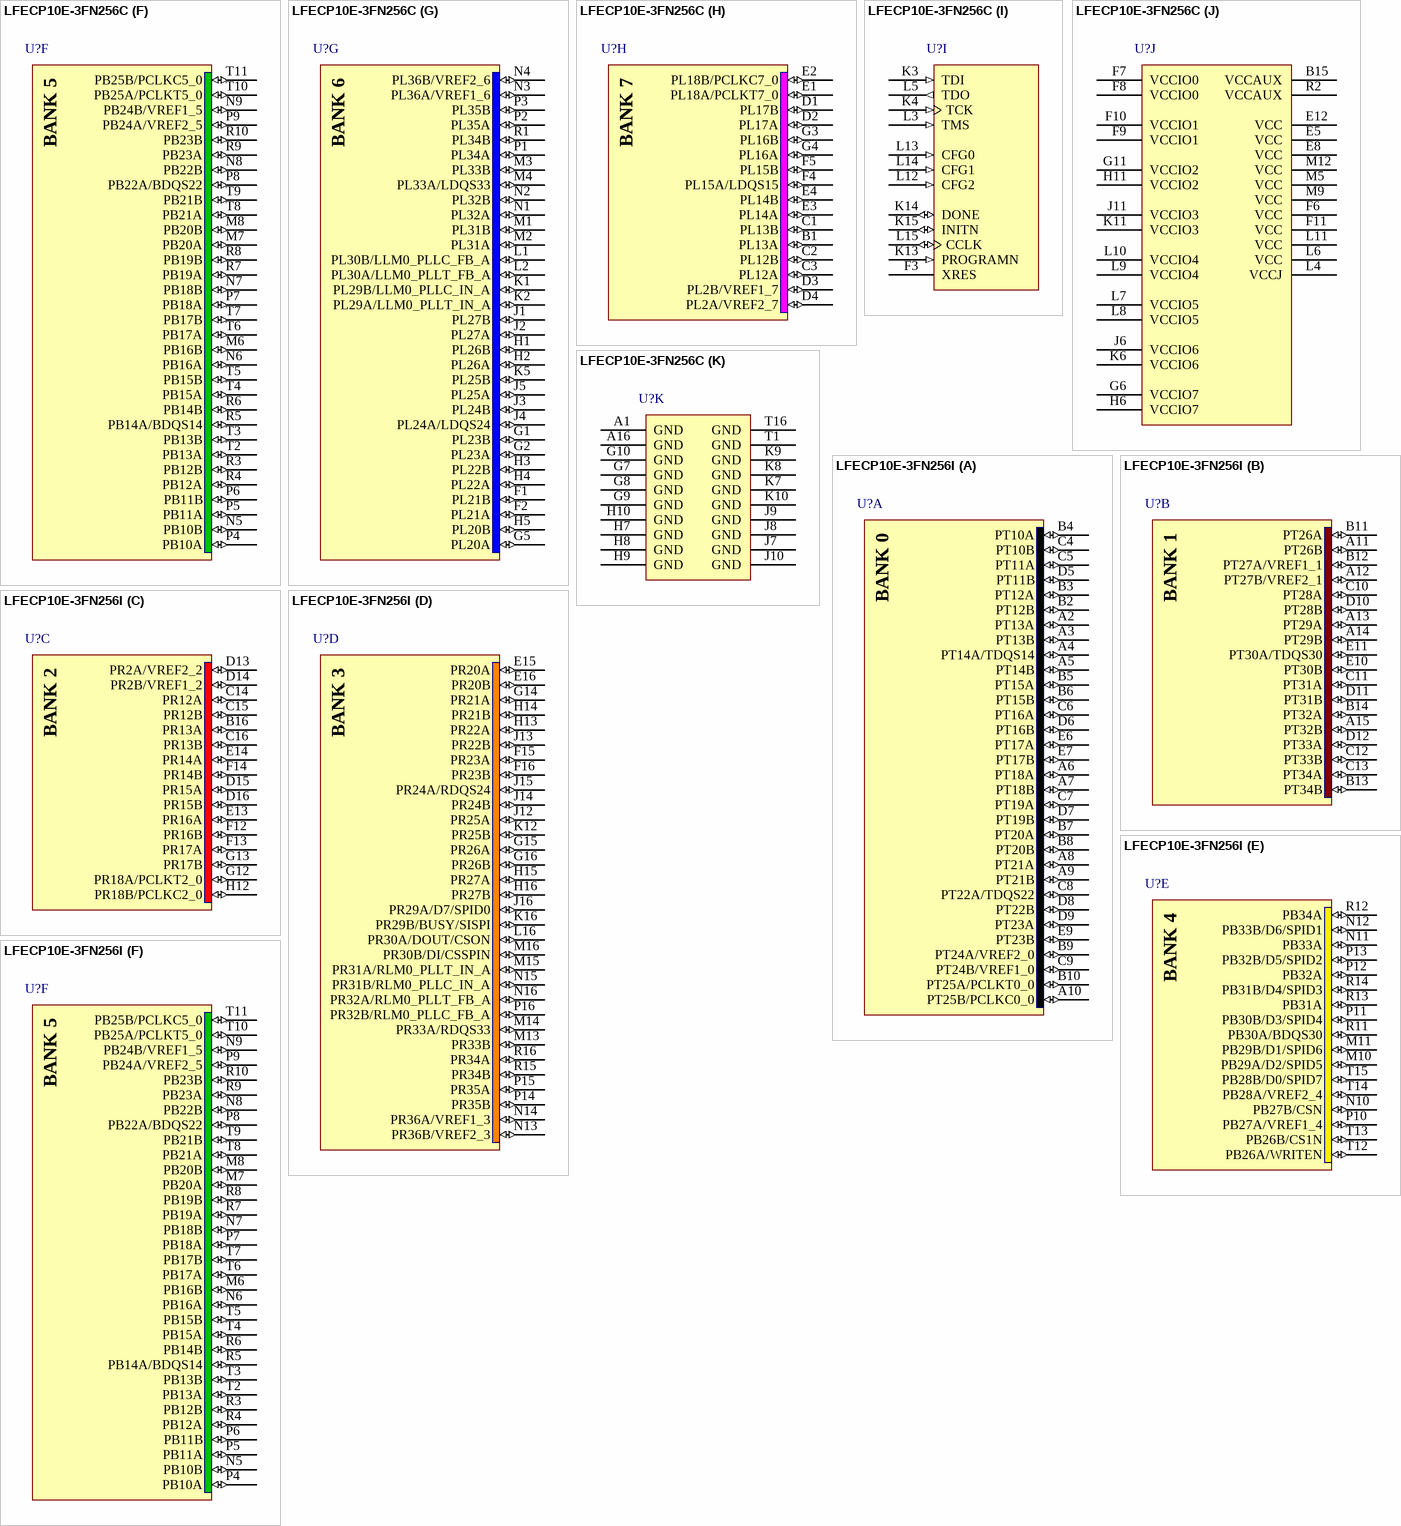
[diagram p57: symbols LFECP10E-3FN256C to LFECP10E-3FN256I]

## LFECP10E-3FN256C
designator U?
ECP 1.2V FPGA, 195 I/Os, 4 PLLs, 10.2K LUTs, 5 sysDSP Blocks, 20 18x18 Multipliers, 256-Pin fpBGA, Pb-Free, Speed Grade 3, Commercial Temperature Grade
footprint fpBGA256 (BGA, 256-Leads, Body 17x17mm, Pitch 1mm)
3D model ECP10E-fpBGA256 (256-Ball Fine Pitch Ball Grid Array (fpBGA256))
part A pins: A2 PT13A (io), A3 PT13B (io), A4 PT14A/TDQS14 (io), A5 PT14B (io), A6 PT18A (io), A7 PT18B (io), A8 PT21A (io), A9 PT21B (io), A10 PT25B/PCLKC0_0 (io), B2 PT12B (io), B3 PT12A (io), B4 PT10A (io), B5 PT15A (io), B6 PT15B (io), B7 PT20A (io), B8 PT20B (io), B9 PT24A/VREF2_0 (io), B10 PT25A/PCLKT0_0 (io), C4 PT10B (io), C5 PT11A (io), C6 PT16A (io), C7 PT19A (io), C8 PT22A/TDQS22 (io), C9 PT24B/VREF1_0 (io), D5 PT11B (io), D6 PT16B (io), D7 PT19B (io), D8 PT22B (io), D9 PT23A (io), E6 PT17A (io), E7 PT17B (io), E9 PT23B (io)
part B pins: A11 PT26B (io), A12 PT27B/VREF2_1 (io), A13 PT29A (io), A14 PT29B (io), A15 PT32B (io), B11 PT26A (io), B12 PT27A/VREF1_1 (io), B13 PT34B (io), B14 PT32A (io), C10 PT28A (io), C11 PT31A (io), C12 PT33B (io), C13 PT34A (io), D10 PT28B (io), D11 PT31B (io), D12 PT33A (io), E10 PT30B (io), E11 PT30A/TDQS30 (io)
part C pins: B16 PR13A (io), C14 PR12A (io), C15 PR12B (io), C16 PR13B (io), D13 PR2A/VREF2_2 (io), D14 PR2B/VREF1_2 (io), D15 PR15A (io), D16 PR15B (io), E13 PR16A (io), E14 PR14A (io), F12 PR16B (io), F13 PR17A (io), F14 PR14B (io), G12 PR18A/PCLKT2_0 (io), G13 PR17B (io), H12 PR18B/PCLKC2_0 (io)
part D pins: E15 PR20A (io), E16 PR20B (io), F15 PR23A (io), F16 PR23B (io), G14 PR21A (io), G15 PR26A (io), G16 PR26B (io), H13 PR22A (io), H14 PR21B (io), H15 PR27A (io), H16 PR27B (io), J12 PR25A (io), J13 PR22B (io), J14 PR24B (io), J15 PR24A/RDQS24 (io), J16 PR29A/D7/SPID0 (io), K12 PR25B (io), K16 PR29B/BUSY/SISPI (io), L16 PR30A/DOUT/CSON (io), M13 PR33B (io), M14 PR33A/RDQS33 (io), M15 PR31A/RLM0_PLLT_IN_A (io), M16 PR30B/DI/CSSPIN (io), N13 PR36B/VREF2_3 (io), N14 PR36A/VREF1_3 (io), N15 PR31B/RLM0_PLLC_IN_A (io), N16 PR32A/RLM0_PLLT_FB_A (io), P14 PR35B (io), P15 PR35A (io), P16 PR32B/RLM0_PLLC_FB_A (io), R15 PR34B (io), R16 PR34A (io)
part E pins: M10 PB29A/D2/SPID5 (io), M11 PB29B/D1/SPID6 (io), N10 PB27B/CSN (io), N11 PB33A (io), N12 PB33B/D6/SPID1 (io), P10 PB27A/VREF1_4 (io), P11 PB30B/D3/SPID4 (io), P12 PB32A (io), P13 PB32B/D5/SPID2 (io), R11 PB30A/BDQS30 (io), R12 PB34A (io), R13 PB31A (io), R14 PB31B/D4/SPID3 (io), T12 PB26A/WRITEN (io), T13 PB26B/CS1N (io), T14 PB28A/VREF2_4 (io), T15 PB28B/D0/SPID7 (io)
part F pins: M6 PB16B (io), M7 PB20A (io), M8 PB20B (io), N5 PB10B (io), N6 PB16A (io), N7 PB18B (io), N8 PB22B (io), N9 PB24B/VREF1_5 (io), P4 PB10A (io), P5 PB11A (io), P6 PB11B (io), P7 PB18A (io), P8 PB22A/BDQS22 (io), P9 PB24A/VREF2_5 (io), R3 PB12B (io), R4 PB12A (io), R5 PB14A/BDQS14 (io), R6 PB14B (io), R7 PB19A (io), R8 PB19B (io), R9 PB23A (io), R10 PB23B (io), T2 PB13A (io), T3 PB13B (io), T4 PB15A (io), T5 PB15B (io), T6 PB17A (io), T7 PB17B (io), T8 PB21A (io), T9 PB21B (io), T10 PB25A/PCLKT5_0 (io), T11 PB25B/PCLKC5_0 (io)
part G pins: F1 PL21B (io), F2 PL21A (io), G1 PL23B (io), G2 PL23A (io), G5 PL20A (io), H1 PL26B (io), H2 PL26A (io), H3 PL22B (io), H4 PL22A (io), H5 PL20B (io), J1 PL27B (io), J2 PL27A (io), J3 PL24B (io), J4 PL24A/LDQS24 (io), J5 PL25A (io), K1 PL29B/LLM0_PLLC_IN_A (io), K2 PL29A/LLM0_PLLT_IN_A (io), K5 PL25B (io), L1 PL30B/LLM0_PLLC_FB_A (io), L2 PL30A/LLM0_PLLT_FB_A (io), M1 PL31B (io), M2 PL31A (io), M3 PL33B (io), M4 PL33A/LDQS33 (io), N1 PL32A (io), N2 PL32B (io), N3 PL36A/VREF1_6 (io), N4 PL36B/VREF2_6 (io), P1 PL34A (io), P2 PL35A (io), P3 PL35B (io), R1 PL34B (io)
part H pins: B1 PL13A (io), C1 PL13B (io), C2 PL12B (io), C3 PL12A (io), D1 PL17B (io), D2 PL17A (io), D3 PL2B/VREF1_7 (io), D4 PL2A/VREF2_7 (io), E1 PL18A/PCLKT7_0 (io), E2 PL18B/PCLKC7_0 (io), E3 PL14A (io), E4 PL14B (io), F4 PL15A/LDQS15 (io), F5 PL15B (io), G3 PL16B (io), G4 PL16A (io)
part I pins: F3 XRES, K3 TDI (in), K4 TCK (in), K13 PROGRAMN (in), K14 DONE (io), K15 INITN (io), L3 TMS (in), L5 TDO (out), L12 CFG2 (in), L13 CFG0 (in), L14 CFG1 (in), L15 CCLK (io)
part J pins: B15 VCCAUX (power), E5 VCC (power), E8 VCC (power), E12 VCC (power), F6 VCC (power), F7 VCCIO0 (power), F8 VCCIO0 (power), F9 VCCIO1 (power), F10 VCCIO1 (power), F11 VCC (power), G6 VCCIO7 (power), G11 VCCIO2 (power), H6 VCCIO7 (power), H11 VCCIO2 (power), J6 VCCIO6 (power), J11 VCCIO3 (power), K6 VCCIO6 (power), K11 VCCIO3 (power), L4 VCCJ (power), L6 VCC (power), L7 VCCIO5 (power), L8 VCCIO5 (power), L9 VCCIO4 (power), L10 VCCIO4 (power), L11 VCC (power), M5 VCC (power), M9 VCC (power), M12 VCC (power), R2 VCCAUX (power)
part K pins: A1 GND (power), A16 GND (power), G7 GND (power), G8 GND (power), G9 GND (power), G10 GND (power), H7 GND (power), H8 GND (power), H9 GND (power), H10 GND (power), J7 GND (power), J8 GND (power), J9 GND (power), J10 GND (power), K7 GND (power), K8 GND (power), K9 GND (power), K10 GND (power), T1 GND (power), T16 GND (power)

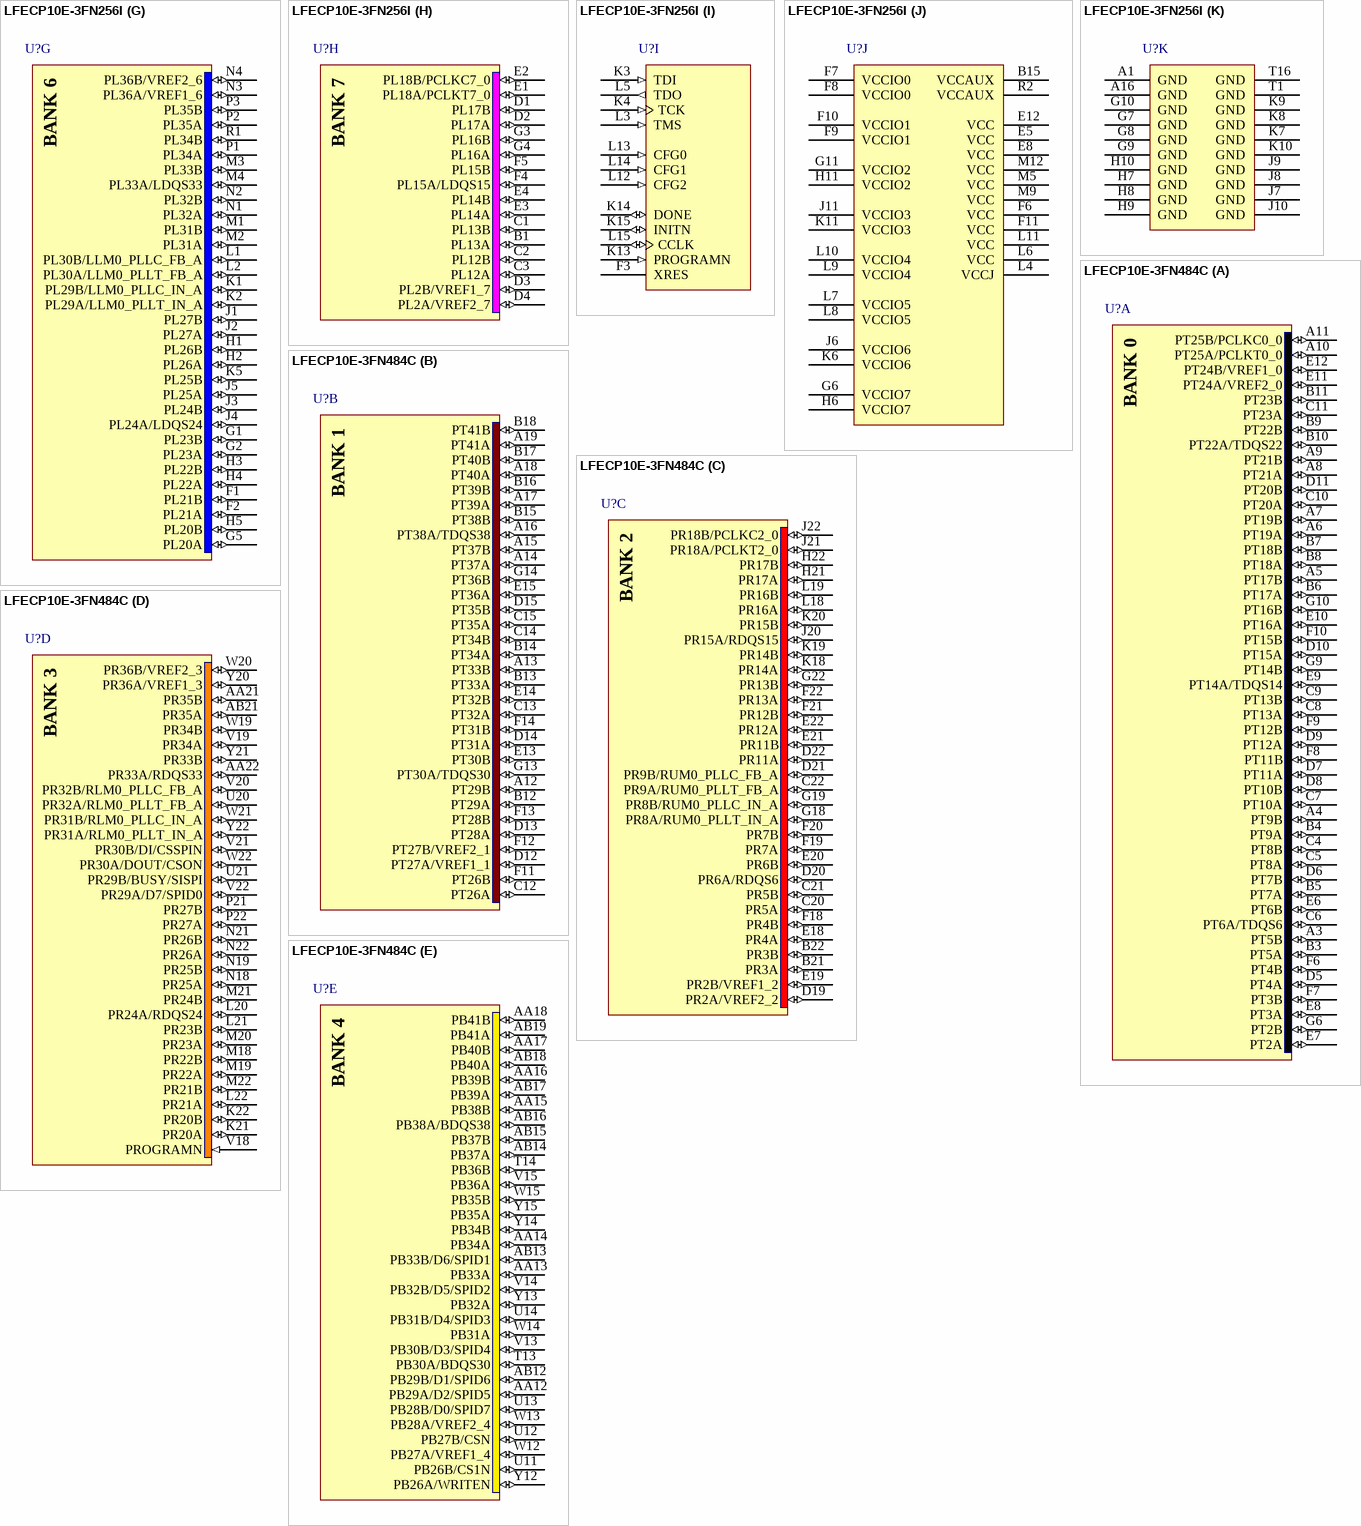
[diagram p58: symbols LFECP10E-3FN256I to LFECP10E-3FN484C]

## LFECP10E-3FN256I
designator U?
ECP 1.2V FPGA, 195 I/Os, 4 PLLs, 10.2K LUTs, 5 sysDSP Blocks, 20 18x18 Multipliers, 256-Pin fpBGA, Pb-Free, Speed Grade 3, Industrial Temperature Grade
footprint fpBGA256 (BGA, 256-Leads, Body 17x17mm, Pitch 1mm)
3D model ECP10E-fpBGA256 (256-Ball Fine Pitch Ball Grid Array (fpBGA256))
part A pins: A2 PT13A (io), A3 PT13B (io), A4 PT14A/TDQS14 (io), A5 PT14B (io), A6 PT18A (io), A7 PT18B (io), A8 PT21A (io), A9 PT21B (io), A10 PT25B/PCLKC0_0 (io), B2 PT12B (io), B3 PT12A (io), B4 PT10A (io), B5 PT15A (io), B6 PT15B (io), B7 PT20A (io), B8 PT20B (io), B9 PT24A/VREF2_0 (io), B10 PT25A/PCLKT0_0 (io), C4 PT10B (io), C5 PT11A (io), C6 PT16A (io), C7 PT19A (io), C8 PT22A/TDQS22 (io), C9 PT24B/VREF1_0 (io), D5 PT11B (io), D6 PT16B (io), D7 PT19B (io), D8 PT22B (io), D9 PT23A (io), E6 PT17A (io), E7 PT17B (io), E9 PT23B (io)
part B pins: A11 PT26B (io), A12 PT27B/VREF2_1 (io), A13 PT29A (io), A14 PT29B (io), A15 PT32B (io), B11 PT26A (io), B12 PT27A/VREF1_1 (io), B13 PT34B (io), B14 PT32A (io), C10 PT28A (io), C11 PT31A (io), C12 PT33B (io), C13 PT34A (io), D10 PT28B (io), D11 PT31B (io), D12 PT33A (io), E10 PT30B (io), E11 PT30A/TDQS30 (io)
part C pins: B16 PR13A (io), C14 PR12A (io), C15 PR12B (io), C16 PR13B (io), D13 PR2A/VREF2_2 (io), D14 PR2B/VREF1_2 (io), D15 PR15A (io), D16 PR15B (io), E13 PR16A (io), E14 PR14A (io), F12 PR16B (io), F13 PR17A (io), F14 PR14B (io), G12 PR18A/PCLKT2_0 (io), G13 PR17B (io), H12 PR18B/PCLKC2_0 (io)
part D pins: E15 PR20A (io), E16 PR20B (io), F15 PR23A (io), F16 PR23B (io), G14 PR21A (io), G15 PR26A (io), G16 PR26B (io), H13 PR22A (io), H14 PR21B (io), H15 PR27A (io), H16 PR27B (io), J12 PR25A (io), J13 PR22B (io), J14 PR24B (io), J15 PR24A/RDQS24 (io), J16 PR29A/D7/SPID0 (io), K12 PR25B (io), K16 PR29B/BUSY/SISPI (io), L16 PR30A/DOUT/CSON (io), M13 PR33B (io), M14 PR33A/RDQS33 (io), M15 PR31A/RLM0_PLLT_IN_A (io), M16 PR30B/DI/CSSPIN (io), N13 PR36B/VREF2_3 (io), N14 PR36A/VREF1_3 (io), N15 PR31B/RLM0_PLLC_IN_A (io), N16 PR32A/RLM0_PLLT_FB_A (io), P14 PR35B (io), P15 PR35A (io), P16 PR32B/RLM0_PLLC_FB_A (io), R15 PR34B (io), R16 PR34A (io)
part E pins: M10 PB29A/D2/SPID5 (io), M11 PB29B/D1/SPID6 (io), N10 PB27B/CSN (io), N11 PB33A (io), N12 PB33B/D6/SPID1 (io), P10 PB27A/VREF1_4 (io), P11 PB30B/D3/SPID4 (io), P12 PB32A (io), P13 PB32B/D5/SPID2 (io), R11 PB30A/BDQS30 (io), R12 PB34A (io), R13 PB31A (io), R14 PB31B/D4/SPID3 (io), T12 PB26A/WRITEN (io), T13 PB26B/CS1N (io), T14 PB28A/VREF2_4 (io), T15 PB28B/D0/SPID7 (io)
part F pins: M6 PB16B (io), M7 PB20A (io), M8 PB20B (io), N5 PB10B (io), N6 PB16A (io), N7 PB18B (io), N8 PB22B (io), N9 PB24B/VREF1_5 (io), P4 PB10A (io), P5 PB11A (io), P6 PB11B (io), P7 PB18A (io), P8 PB22A/BDQS22 (io), P9 PB24A/VREF2_5 (io), R3 PB12B (io), R4 PB12A (io), R5 PB14A/BDQS14 (io), R6 PB14B (io), R7 PB19A (io), R8 PB19B (io), R9 PB23A (io), R10 PB23B (io), T2 PB13A (io), T3 PB13B (io), T4 PB15A (io), T5 PB15B (io), T6 PB17A (io), T7 PB17B (io), T8 PB21A (io), T9 PB21B (io), T10 PB25A/PCLKT5_0 (io), T11 PB25B/PCLKC5_0 (io)
part G pins: F1 PL21B (io), F2 PL21A (io), G1 PL23B (io), G2 PL23A (io), G5 PL20A (io), H1 PL26B (io), H2 PL26A (io), H3 PL22B (io), H4 PL22A (io), H5 PL20B (io), J1 PL27B (io), J2 PL27A (io), J3 PL24B (io), J4 PL24A/LDQS24 (io), J5 PL25A (io), K1 PL29B/LLM0_PLLC_IN_A (io), K2 PL29A/LLM0_PLLT_IN_A (io), K5 PL25B (io), L1 PL30B/LLM0_PLLC_FB_A (io), L2 PL30A/LLM0_PLLT_FB_A (io), M1 PL31B (io), M2 PL31A (io), M3 PL33B (io), M4 PL33A/LDQS33 (io), N1 PL32A (io), N2 PL32B (io), N3 PL36A/VREF1_6 (io), N4 PL36B/VREF2_6 (io), P1 PL34A (io), P2 PL35A (io), P3 PL35B (io), R1 PL34B (io)
part H pins: B1 PL13A (io), C1 PL13B (io), C2 PL12B (io), C3 PL12A (io), D1 PL17B (io), D2 PL17A (io), D3 PL2B/VREF1_7 (io), D4 PL2A/VREF2_7 (io), E1 PL18A/PCLKT7_0 (io), E2 PL18B/PCLKC7_0 (io), E3 PL14A (io), E4 PL14B (io), F4 PL15A/LDQS15 (io), F5 PL15B (io), G3 PL16B (io), G4 PL16A (io)
part I pins: F3 XRES, K3 TDI (in), K4 TCK (in), K13 PROGRAMN (in), K14 DONE (io), K15 INITN (io), L3 TMS (in), L5 TDO (out), L12 CFG2 (in), L13 CFG0 (in), L14 CFG1 (in), L15 CCLK (io)
part J pins: B15 VCCAUX (power), E5 VCC (power), E8 VCC (power), E12 VCC (power), F6 VCC (power), F7 VCCIO0 (power), F8 VCCIO0 (power), F9 VCCIO1 (power), F10 VCCIO1 (power), F11 VCC (power), G6 VCCIO7 (power), G11 VCCIO2 (power), H6 VCCIO7 (power), H11 VCCIO2 (power), J6 VCCIO6 (power), J11 VCCIO3 (power), K6 VCCIO6 (power), K11 VCCIO3 (power), L4 VCCJ (power), L6 VCC (power), L7 VCCIO5 (power), L8 VCCIO5 (power), L9 VCCIO4 (power), L10 VCCIO4 (power), L11 VCC (power), M5 VCC (power), M9 VCC (power), M12 VCC (power), R2 VCCAUX (power)
part K pins: A1 GND (power), A16 GND (power), G7 GND (power), G8 GND (power), G9 GND (power), G10 GND (power), H7 GND (power), H8 GND (power), H9 GND (power), H10 GND (power), J7 GND (power), J8 GND (power), J9 GND (power), J10 GND (power), K7 GND (power), K8 GND (power), K9 GND (power), K10 GND (power), T1 GND (power), T16 GND (power)

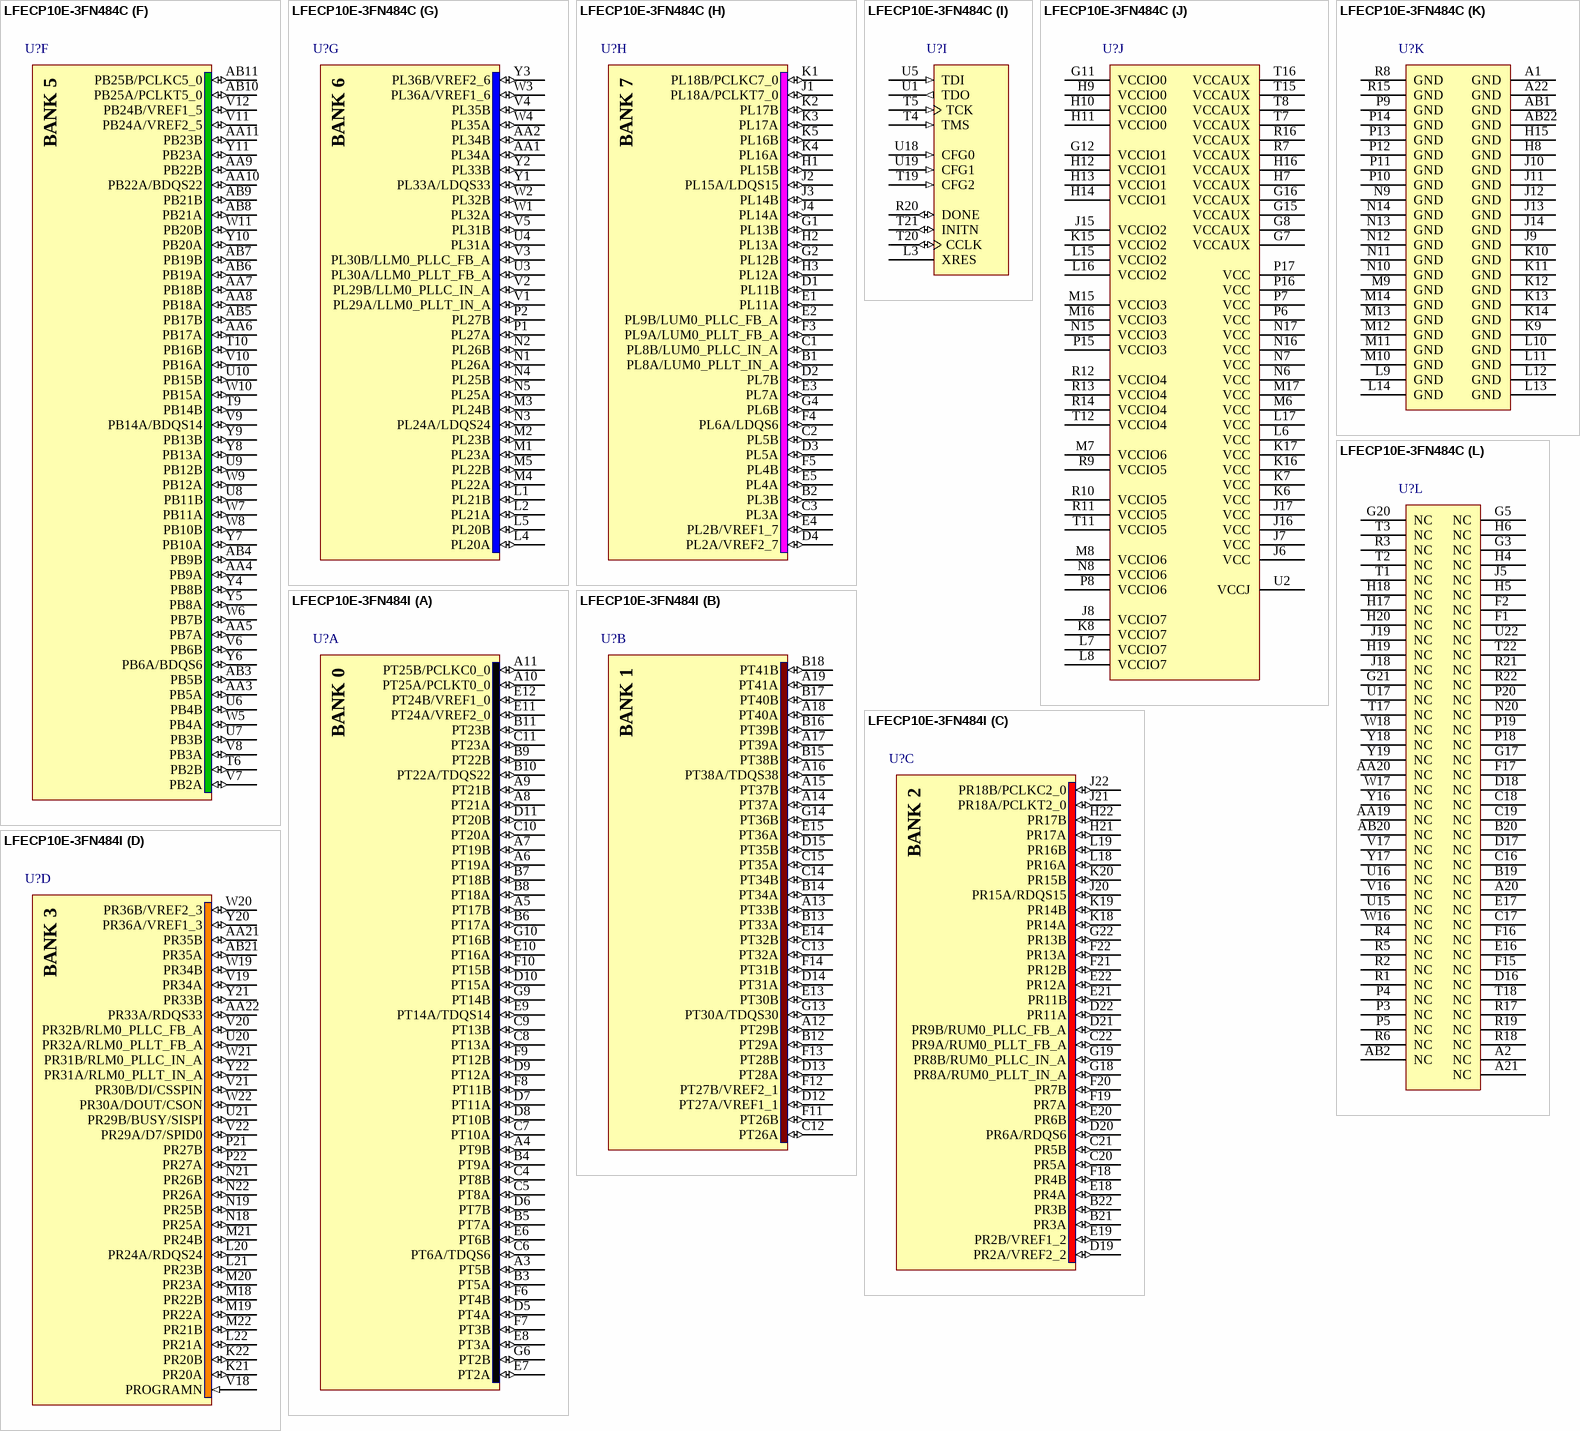
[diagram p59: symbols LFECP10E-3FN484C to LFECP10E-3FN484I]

## LFECP10E-3FN484C
designator U?
ECP 1.2V FPGA, 228 I/Os, 4 PLLs, 10.2K LUTs, 5 sysDSP Blocks, 20 18x18 Multipliers, 484-Pin fpBGA, Pb-Free, Speed Grade 3, Commercial Temperature Grade
footprint fpBGA484 (BGA, 484-Leads, Body 23x23mm, Pitch 1mm)
3D model ECP10E-fpBGA484 (484-Ball Fine Pitch Ball Grid Array (fpBGA484))
part A pins: A3 PT5B (io), A4 PT9B (io), A5 PT17B (io), A6 PT19A (io), A7 PT19B (io), A8 PT21A (io), A9 PT21B (io), A10 PT25A/PCLKT0_0 (io), A11 PT25B/PCLKC0_0 (io), B3 PT5A (io), B4 PT9A (io), B5 PT7A (io), B6 PT17A (io), B7 PT18B (io), B8 PT18A (io), B9 PT22B (io), B10 PT22A/TDQS22 (io), B11 PT23B (io), C4 PT8B (io), C5 PT8A (io), C6 PT6A/TDQS6 (io), C7 PT10A (io), C8 PT13A (io), C9 PT13B (io), C10 PT20A (io), C11 PT23A (io), D5 PT4A (io), D6 PT7B (io), D7 PT11A (io), D8 PT10B (io), D9 PT12A (io), D10 PT15A (io), D11 PT20B (io), E6 PT6B (io), E7 PT2A (io), E8 PT3A (io), E9 PT14A/TDQS14 (io), E10 PT16A (io), E11 PT24A/VREF2_0 (io), E12 PT24B/VREF1_0 (io), F6 PT4B (io), F7 PT3B (io), F8 PT11B (io), F9 PT12B (io), F10 PT15B (io), G6 PT2B (io), G9 PT14B (io), G10 PT16B (io)
part B pins: A12 PT29B (io), A13 PT33B (io), A14 PT37A (io), A15 PT37B (io), A16 PT38A/TDQS38 (io), A17 PT39A (io), A18 PT40A (io), A19 PT41A (io), B12 PT29A (io), B13 PT33A (io), B14 PT34A (io), B15 PT38B (io), B16 PT39B (io), B17 PT40B (io), B18 PT41B (io), C12 PT26A (io), C13 PT32A (io), C14 PT34B (io), C15 PT35A (io), D12 PT27A/VREF1_1 (io), D13 PT28A (io), D14 PT31A (io), D15 PT35B (io), E13 PT30B (io), E14 PT32B (io), E15 PT36A (io), F11 PT26B (io), F12 PT27B/VREF2_1 (io), F13 PT28B (io), F14 PT31B (io), G13 PT30A/TDQS30 (io), G14 PT36B (io)
part C pins: B21 PR3A (io), B22 PR3B (io), C20 PR5A (io), C21 PR5B (io), C22 PR9A/RUM0_PLLT_FB_A (io), D19 PR2A/VREF2_2 (io), D20 PR6A/RDQS6 (io), D21 PR9B/RUM0_PLLC_FB_A (io), D22 PR11A (io), E18 PR4A (io), E19 PR2B/VREF1_2 (io), E20 PR6B (io), E21 PR11B (io), E22 PR12A (io), F18 PR4B (io), F19 PR7A (io), F20 PR7B (io), F21 PR12B (io), F22 PR13A (io), G18 PR8A/RUM0_PLLT_IN_A (io), G19 PR8B/RUM0_PLLC_IN_A (io), G22 PR13B (io), H21 PR17A (io), H22 PR17B (io), J20 PR15A/RDQS15 (io), J21 PR18A/PCLKT2_0 (io), J22 PR18B/PCLKC2_0 (io), K18 PR14A (io), K19 PR14B (io), K20 PR15B (io), L18 PR16A (io), L19 PR16B (io)
part D pins: AA21 PR35B (io), AA22 PR33A/RDQS33 (io), AB21 PR35A (io), K21 PR20A (io), K22 PR20B (io), L20 PR24A/RDQS24 (io), L21 PR23B (io), L22 PR21A (io), M18 PR22B (io), M19 PR22A (io), M20 PR23A (io), M21 PR24B (io), M22 PR21B (io), N18 PR25A (io), N19 PR25B (io), N21 PR26B (io), N22 PR26A (io), P21 PR27B (io), P22 PR27A (io), U20 PR32A/RLM0_PLLT_FB_A (io), U21 PR29B/BUSY/SISPI (io), V18 PROGRAMN (in), V19 PR34A (io), V20 PR32B/RLM0_PLLC_FB_A (io), V21 PR30B/DI/CSSPIN (io), V22 PR29A/D7/SPID0 (io), W19 PR34B (io), W20 PR36B/VREF2_3 (io), W21 PR31B/RLM0_PLLC_IN_A (io), W22 PR30A/DOUT/CSON (io), Y20 PR36A/VREF1_3 (io), Y21 PR33B (io), Y22 PR31A/RLM0_PLLT_IN_A (io)
part E pins: AA12 PB29A/D2/SPID5 (io), AA13 PB33A (io), AA14 PB34A (io), AA15 PB38B (io), AA16 PB39B (io), AA17 PB40B (io), AA18 PB41B (io), AB12 PB29B/D1/SPID6 (io), AB13 PB33B/D6/SPID1 (io), AB14 PB37A (io), AB15 PB37B (io), AB16 PB38A/BDQS38 (io), AB17 PB39A (io), AB18 PB40A (io), AB19 PB41A (io), T13 PB30A/BDQS30 (io), T14 PB36B (io), U11 PB26B/CS1N (io), U12 PB27B/CSN (io), U13 PB28B/D0/SPID7 (io), U14 PB31B/D4/SPID3 (io), V13 PB30B/D3/SPID4 (io), V14 PB32B/D5/SPID2 (io), V15 PB36A (io), W12 PB27A/VREF1_4 (io), W13 PB28A/VREF2_4 (io), W14 PB31A (io), W15 PB35B (io), Y12 PB26A/WRITEN (io), Y13 PB32A (io), Y14 PB34B (io), Y15 PB35A (io)
part F pins: AA3 PB5A (io), AA4 PB9A (io), AA5 PB7A (io), AA6 PB17A (io), AA7 PB18B (io), AA8 PB18A (io), AA9 PB22B (io), AA10 PB22A/BDQS22 (io), AA11 PB23B (io), AB3 PB5B (io), AB4 PB9B (io), AB5 PB17B (io), AB6 PB19A (io), AB7 PB19B (io), AB8 PB21A (io), AB9 PB21B (io), AB10 PB25A/PCLKT5_0 (io), AB11 PB25B/PCLKC5_0 (io), T6 PB2B (io), T9 PB14B (io), T10 PB16B (io), U6 PB4B (io), U7 PB3B (io), U8 PB11B (io), U9 PB12B (io), U10 PB15B (io), V6 PB6B (io), V7 PB2A (io), V8 PB3A (io), V9 PB14A/BDQS14 (io), V10 PB16A (io), V11 PB24A/VREF2_5 (io), V12 PB24B/VREF1_5 (io), W5 PB4A (io), W6 PB7B (io), W7 PB11A (io), W8 PB10B (io), W9 PB12A (io), W10 PB15A (io), W11 PB20B (io), Y4 PB8B (io), Y5 PB8A (io), Y6 PB6A/BDQS6 (io), Y7 PB10A (io), Y8 PB13A (io), Y9 PB13B (io), Y10 PB20A (io), Y11 PB23A (io)
part G pins: AA1 PL34A (io), AA2 PL34B (io), L1 PL21B (io), L2 PL21A (io), L4 PL20A (io), L5 PL20B (io), M1 PL23A (io), M2 PL23B (io), M3 PL24B (io), M4 PL22A (io), M5 PL22B (io), N1 PL26A (io), N2 PL26B (io), N3 PL24A/LDQS24 (io), N4 PL25B (io), N5 PL25A (io), P1 PL27A (io), P2 PL27B (io), U3 PL30A/LLM0_PLLT_FB_A (io), U4 PL31A (io), V1 PL29A/LLM0_PLLT_IN_A (io), V2 PL29B/LLM0_PLLC_IN_A (io), V3 PL30B/LLM0_PLLC_FB_A (io), V4 PL35B (io), V5 PL31B (io), W1 PL32A (io), W2 PL32B (io), W3 PL36A/VREF1_6 (io), W4 PL35A (io), Y1 PL33A/LDQS33 (io), Y2 PL33B (io), Y3 PL36B/VREF2_6 (io)
part H pins: B1 PL8A/LUM0_PLLT_IN_A (io), B2 PL3B (io), C1 PL8B/LUM0_PLLC_IN_A (io), C2 PL5B (io), C3 PL3A (io), D1 PL11B (io), D2 PL7B (io), D3 PL5A (io), D4 PL2A/VREF2_7 (io), E1 PL11A (io), E2 PL9B/LUM0_PLLC_FB_A (io), E3 PL7A (io), E4 PL2B/VREF1_7 (io), E5 PL4A (io), F3 PL9A/LUM0_PLLT_FB_A (io), F4 PL6A/LDQS6 (io), F5 PL4B (io), G1 PL13B (io), G2 PL12B (io), G4 PL6B (io), H1 PL15B (io), H2 PL13A (io), H3 PL12A (io), J1 PL18A/PCLKT7_0 (io), J2 PL15A/LDQS15 (io), J3 PL14B (io), J4 PL14A (io), K1 PL18B/PCLKC7_0 (io), K2 PL17B (io), K3 PL17A (io), K4 PL16A (io), K5 PL16B (io)
part I pins: L3 XRES, R20 DONE (io), T4 TMS (in), T5 TCK (in), T19 CFG2 (in), T20 CCLK (io), T21 INITN (io), U1 TDO (out), U5 TDI (in), U18 CFG0 (in), U19 CFG1 (in)
part J pins: G7 VCCAUX (power), G8 VCCAUX (power), G11 VCCIO0 (power), G12 VCCIO1 (power), G15 VCCAUX (power), G16 VCCAUX (power), H7 VCCAUX (power), H9 VCCIO0 (power), H10 VCCIO0 (power), H11 VCCIO0 (power), H12 VCCIO1 (power), H13 VCCIO1 (power), H14 VCCIO1 (power), H16 VCCAUX (power), J6 VCC (power), J7 VCC (power), J8 VCCIO7 (power), J15 VCCIO2 (power), J16 VCC (power), J17 VCC (power), K6 VCC (power), K7 VCC (power), K8 VCCIO7 (power), K15 VCCIO2 (power), K16 VCC (power), K17 VCC (power), L6 VCC (power), L7 VCCIO7 (power), L8 VCCIO7 (power), L15 VCCIO2 (power), L16 VCCIO2 (power), L17 VCC (power), M6 VCC (power), M7 VCCIO6 (power), M8 VCCIO6 (power), M15 VCCIO3 (power), M16 VCCIO3 (power), M17 VCC (power), N6 VCC (power), N7 VCC (power), N8 VCCIO6 (power), N15 VCCIO3 (power), N16 VCC (power), N17 VCC (power), P6 VCC (power), P7 VCC (power), P8 VCCIO6 (power), P15 VCCIO3 (power), P16 VCC (power), P17 VCC (power), R7 VCCAUX (power), R9 VCCIO5 (power), R10 VCCIO5 (power), R11 VCCIO5 (power), R12 VCCIO4 (power), R13 VCCIO4 (power), R14 VCCIO4 (power), R16 VCCAUX (power), T7 VCCAUX (power), T8 VCCAUX (power), T11 VCCIO5 (power), T12 VCCIO4 (power), T15 VCCAUX (power), T16 VCCAUX (power), U2 VCCJ (power)
part K pins: A1 GND (power), A22 GND (power), AB1 GND (power), AB22 GND (power), H8 GND (power), H15 GND (power), J9 GND (power), J10 GND (power), J11 GND (power), J12 GND (power), J13 GND (power), J14 GND (power), K9 GND (power), K10 GND (power), K11 GND (power), K12 GND (power), K13 GND (power), K14 GND (power), L9 GND (power), L10 GND (power), L11 GND (power), L12 GND (power), L13 GND (power), L14 GND (power), M9 GND (power), M10 GND (power), M11 GND (power), M12 GND (power), M13 GND (power), M14 GND (power), N9 GND (power), N10 GND (power), N11 GND (power), N12 GND (power), N13 GND (power), N14 GND (power), P9 GND (power), P10 GND (power), P11 GND (power), P12 GND (power), P13 GND (power), P14 GND (power), R8 GND (power), R15 GND (power)
part L pins: A2 NC, A20 NC, A21 NC, AA19 NC, AA20 NC, AB2 NC, AB20 NC, B19 NC, B20 NC, C16 NC, C17 NC, C18 NC, C19 NC, D16 NC, D17 NC, D18 NC, E16 NC, E17 NC, F1 NC, F2 NC, F15 NC, F16 NC, F17 NC, G3 NC, G5 NC, G17 NC, G20 NC, G21 NC, H4 NC, H5 NC, H6 NC, H17 NC, H18 NC, H19 NC, H20 NC, J5 NC, J18 NC, J19 NC, N20 NC, P3 NC, P4 NC, P5 NC, P18 NC, P19 NC, P20 NC, R1 NC, R2 NC, R3 NC, R4 NC, R5 NC, R6 NC, R17 NC, R18 NC, R19 NC, R21 NC, R22 NC, T1 NC, T2 NC, T3 NC, T17 NC, T18 NC, T22 NC, U15 NC, U16 NC, U17 NC, U22 NC, V16 NC, V17 NC, W16 NC, W17 NC, W18 NC, Y16 NC, Y17 NC, Y18 NC, Y19 NC

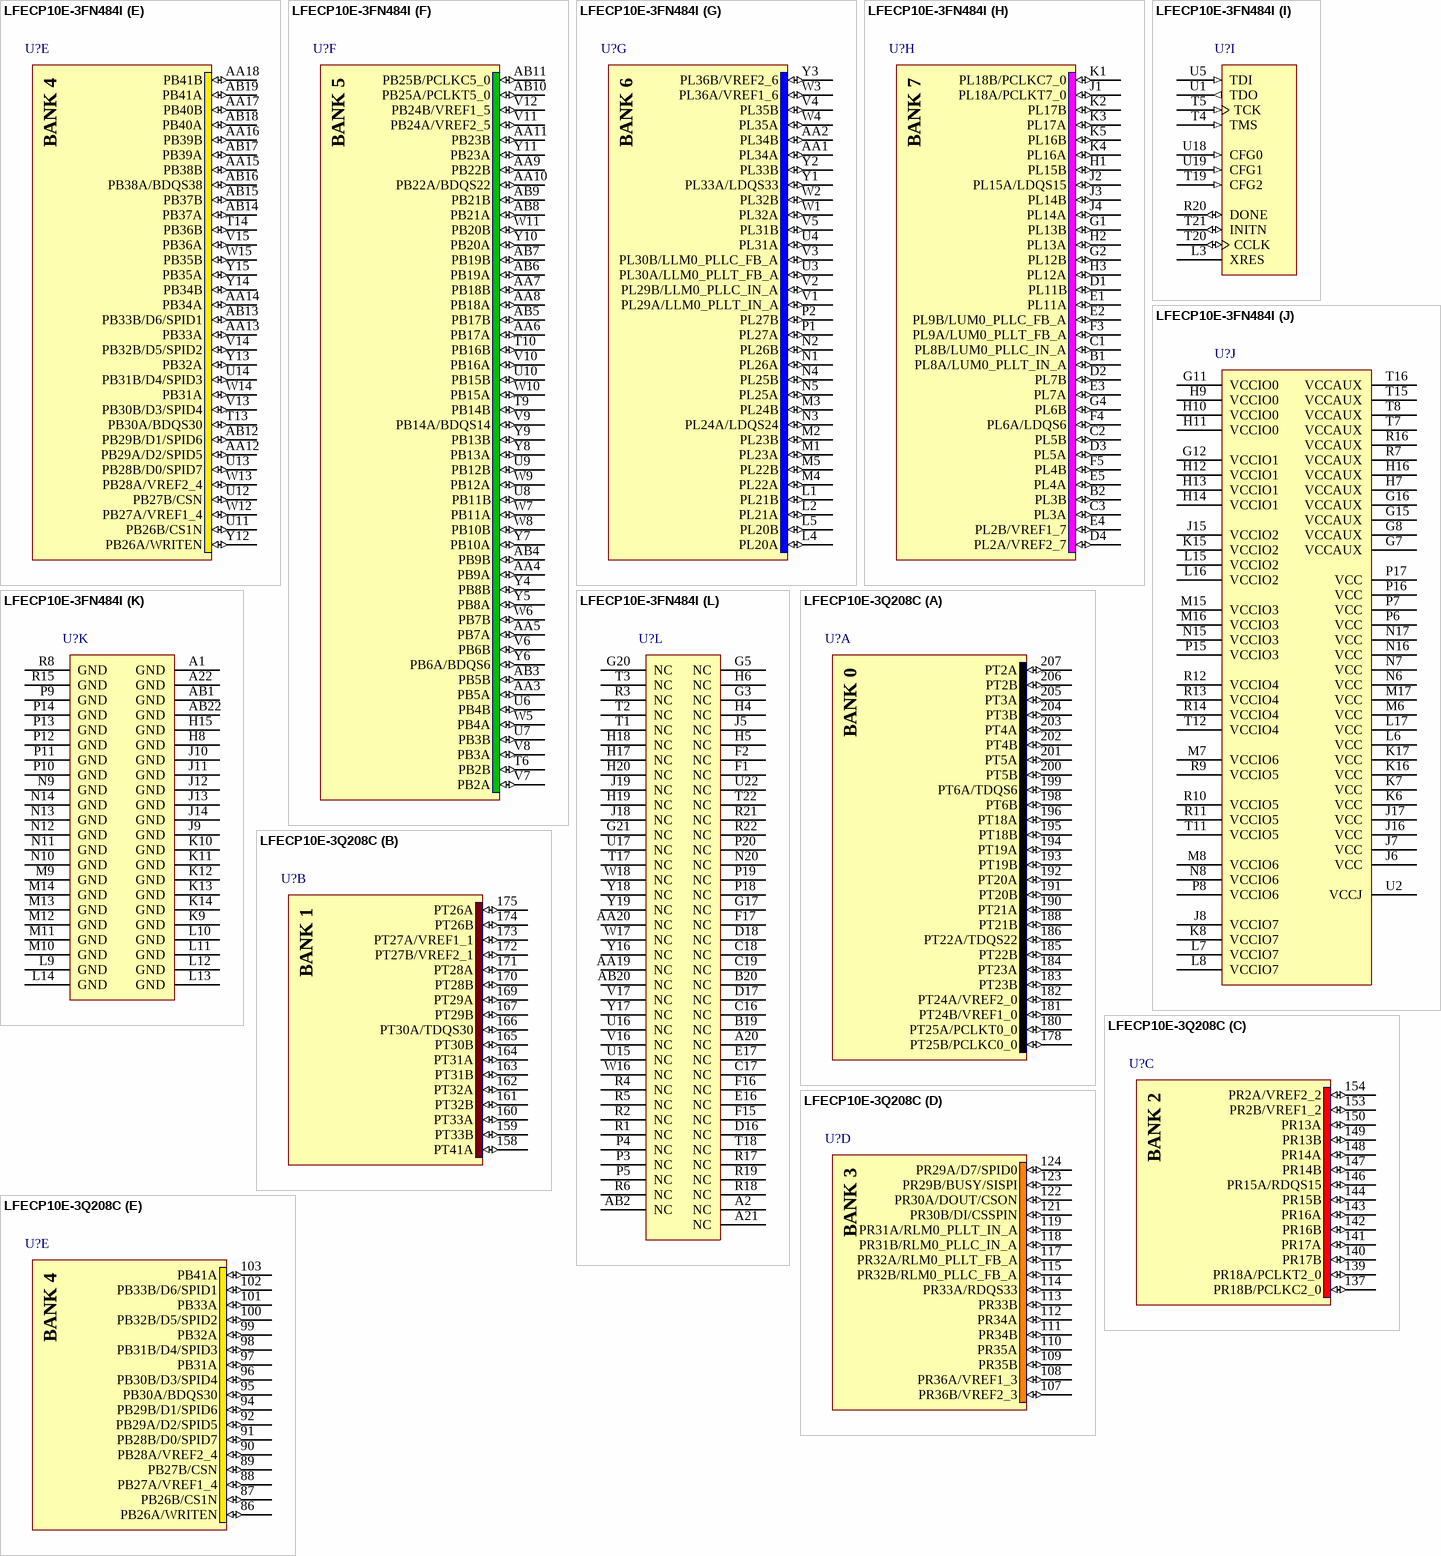
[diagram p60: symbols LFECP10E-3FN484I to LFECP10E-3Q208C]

## LFECP10E-3FN484I
designator U?
ECP 1.2V FPGA, 228 I/Os, 4 PLLs, 10.2K LUTs, 5 sysDSP Blocks, 20 18x18 Multipliers, 484-Pin fpBGA, Pb-Free, Speed Grade 3, Industrial Temperature Grade
footprint fpBGA484 (BGA, 484-Leads, Body 23x23mm, Pitch 1mm)
3D model ECP10E-fpBGA484 (484-Ball Fine Pitch Ball Grid Array (fpBGA484))
part A pins: A3 PT5B (io), A4 PT9B (io), A5 PT17B (io), A6 PT19A (io), A7 PT19B (io), A8 PT21A (io), A9 PT21B (io), A10 PT25A/PCLKT0_0 (io), A11 PT25B/PCLKC0_0 (io), B3 PT5A (io), B4 PT9A (io), B5 PT7A (io), B6 PT17A (io), B7 PT18B (io), B8 PT18A (io), B9 PT22B (io), B10 PT22A/TDQS22 (io), B11 PT23B (io), C4 PT8B (io), C5 PT8A (io), C6 PT6A/TDQS6 (io), C7 PT10A (io), C8 PT13A (io), C9 PT13B (io), C10 PT20A (io), C11 PT23A (io), D5 PT4A (io), D6 PT7B (io), D7 PT11A (io), D8 PT10B (io), D9 PT12A (io), D10 PT15A (io), D11 PT20B (io), E6 PT6B (io), E7 PT2A (io), E8 PT3A (io), E9 PT14A/TDQS14 (io), E10 PT16A (io), E11 PT24A/VREF2_0 (io), E12 PT24B/VREF1_0 (io), F6 PT4B (io), F7 PT3B (io), F8 PT11B (io), F9 PT12B (io), F10 PT15B (io), G6 PT2B (io), G9 PT14B (io), G10 PT16B (io)
part B pins: A12 PT29B (io), A13 PT33B (io), A14 PT37A (io), A15 PT37B (io), A16 PT38A/TDQS38 (io), A17 PT39A (io), A18 PT40A (io), A19 PT41A (io), B12 PT29A (io), B13 PT33A (io), B14 PT34A (io), B15 PT38B (io), B16 PT39B (io), B17 PT40B (io), B18 PT41B (io), C12 PT26A (io), C13 PT32A (io), C14 PT34B (io), C15 PT35A (io), D12 PT27A/VREF1_1 (io), D13 PT28A (io), D14 PT31A (io), D15 PT35B (io), E13 PT30B (io), E14 PT32B (io), E15 PT36A (io), F11 PT26B (io), F12 PT27B/VREF2_1 (io), F13 PT28B (io), F14 PT31B (io), G13 PT30A/TDQS30 (io), G14 PT36B (io)
part C pins: B21 PR3A (io), B22 PR3B (io), C20 PR5A (io), C21 PR5B (io), C22 PR9A/RUM0_PLLT_FB_A (io), D19 PR2A/VREF2_2 (io), D20 PR6A/RDQS6 (io), D21 PR9B/RUM0_PLLC_FB_A (io), D22 PR11A (io), E18 PR4A (io), E19 PR2B/VREF1_2 (io), E20 PR6B (io), E21 PR11B (io), E22 PR12A (io), F18 PR4B (io), F19 PR7A (io), F20 PR7B (io), F21 PR12B (io), F22 PR13A (io), G18 PR8A/RUM0_PLLT_IN_A (io), G19 PR8B/RUM0_PLLC_IN_A (io), G22 PR13B (io), H21 PR17A (io), H22 PR17B (io), J20 PR15A/RDQS15 (io), J21 PR18A/PCLKT2_0 (io), J22 PR18B/PCLKC2_0 (io), K18 PR14A (io), K19 PR14B (io), K20 PR15B (io), L18 PR16A (io), L19 PR16B (io)
part D pins: AA21 PR35B (io), AA22 PR33A/RDQS33 (io), AB21 PR35A (io), K21 PR20A (io), K22 PR20B (io), L20 PR24A/RDQS24 (io), L21 PR23B (io), L22 PR21A (io), M18 PR22B (io), M19 PR22A (io), M20 PR23A (io), M21 PR24B (io), M22 PR21B (io), N18 PR25A (io), N19 PR25B (io), N21 PR26B (io), N22 PR26A (io), P21 PR27B (io), P22 PR27A (io), U20 PR32A/RLM0_PLLT_FB_A (io), U21 PR29B/BUSY/SISPI (io), V18 PROGRAMN (in), V19 PR34A (io), V20 PR32B/RLM0_PLLC_FB_A (io), V21 PR30B/DI/CSSPIN (io), V22 PR29A/D7/SPID0 (io), W19 PR34B (io), W20 PR36B/VREF2_3 (io), W21 PR31B/RLM0_PLLC_IN_A (io), W22 PR30A/DOUT/CSON (io), Y20 PR36A/VREF1_3 (io), Y21 PR33B (io), Y22 PR31A/RLM0_PLLT_IN_A (io)
part E pins: AA12 PB29A/D2/SPID5 (io), AA13 PB33A (io), AA14 PB34A (io), AA15 PB38B (io), AA16 PB39B (io), AA17 PB40B (io), AA18 PB41B (io), AB12 PB29B/D1/SPID6 (io), AB13 PB33B/D6/SPID1 (io), AB14 PB37A (io), AB15 PB37B (io), AB16 PB38A/BDQS38 (io), AB17 PB39A (io), AB18 PB40A (io), AB19 PB41A (io), T13 PB30A/BDQS30 (io), T14 PB36B (io), U11 PB26B/CS1N (io), U12 PB27B/CSN (io), U13 PB28B/D0/SPID7 (io), U14 PB31B/D4/SPID3 (io), V13 PB30B/D3/SPID4 (io), V14 PB32B/D5/SPID2 (io), V15 PB36A (io), W12 PB27A/VREF1_4 (io), W13 PB28A/VREF2_4 (io), W14 PB31A (io), W15 PB35B (io), Y12 PB26A/WRITEN (io), Y13 PB32A (io), Y14 PB34B (io), Y15 PB35A (io)
part F pins: AA3 PB5A (io), AA4 PB9A (io), AA5 PB7A (io), AA6 PB17A (io), AA7 PB18B (io), AA8 PB18A (io), AA9 PB22B (io), AA10 PB22A/BDQS22 (io), AA11 PB23B (io), AB3 PB5B (io), AB4 PB9B (io), AB5 PB17B (io), AB6 PB19A (io), AB7 PB19B (io), AB8 PB21A (io), AB9 PB21B (io), AB10 PB25A/PCLKT5_0 (io), AB11 PB25B/PCLKC5_0 (io), T6 PB2B (io), T9 PB14B (io), T10 PB16B (io), U6 PB4B (io), U7 PB3B (io), U8 PB11B (io), U9 PB12B (io), U10 PB15B (io), V6 PB6B (io), V7 PB2A (io), V8 PB3A (io), V9 PB14A/BDQS14 (io), V10 PB16A (io), V11 PB24A/VREF2_5 (io), V12 PB24B/VREF1_5 (io), W5 PB4A (io), W6 PB7B (io), W7 PB11A (io), W8 PB10B (io), W9 PB12A (io), W10 PB15A (io), W11 PB20B (io), Y4 PB8B (io), Y5 PB8A (io), Y6 PB6A/BDQS6 (io), Y7 PB10A (io), Y8 PB13A (io), Y9 PB13B (io), Y10 PB20A (io), Y11 PB23A (io)
part G pins: AA1 PL34A (io), AA2 PL34B (io), L1 PL21B (io), L2 PL21A (io), L4 PL20A (io), L5 PL20B (io), M1 PL23A (io), M2 PL23B (io), M3 PL24B (io), M4 PL22A (io), M5 PL22B (io), N1 PL26A (io), N2 PL26B (io), N3 PL24A/LDQS24 (io), N4 PL25B (io), N5 PL25A (io), P1 PL27A (io), P2 PL27B (io), U3 PL30A/LLM0_PLLT_FB_A (io), U4 PL31A (io), V1 PL29A/LLM0_PLLT_IN_A (io), V2 PL29B/LLM0_PLLC_IN_A (io), V3 PL30B/LLM0_PLLC_FB_A (io), V4 PL35B (io), V5 PL31B (io), W1 PL32A (io), W2 PL32B (io), W3 PL36A/VREF1_6 (io), W4 PL35A (io), Y1 PL33A/LDQS33 (io), Y2 PL33B (io), Y3 PL36B/VREF2_6 (io)
part H pins: B1 PL8A/LUM0_PLLT_IN_A (io), B2 PL3B (io), C1 PL8B/LUM0_PLLC_IN_A (io), C2 PL5B (io), C3 PL3A (io), D1 PL11B (io), D2 PL7B (io), D3 PL5A (io), D4 PL2A/VREF2_7 (io), E1 PL11A (io), E2 PL9B/LUM0_PLLC_FB_A (io), E3 PL7A (io), E4 PL2B/VREF1_7 (io), E5 PL4A (io), F3 PL9A/LUM0_PLLT_FB_A (io), F4 PL6A/LDQS6 (io), F5 PL4B (io), G1 PL13B (io), G2 PL12B (io), G4 PL6B (io), H1 PL15B (io), H2 PL13A (io), H3 PL12A (io), J1 PL18A/PCLKT7_0 (io), J2 PL15A/LDQS15 (io), J3 PL14B (io), J4 PL14A (io), K1 PL18B/PCLKC7_0 (io), K2 PL17B (io), K3 PL17A (io), K4 PL16A (io), K5 PL16B (io)
part I pins: L3 XRES, R20 DONE (io), T4 TMS (in), T5 TCK (in), T19 CFG2 (in), T20 CCLK (io), T21 INITN (io), U1 TDO (out), U5 TDI (in), U18 CFG0 (in), U19 CFG1 (in)
part J pins: G7 VCCAUX (power), G8 VCCAUX (power), G11 VCCIO0 (power), G12 VCCIO1 (power), G15 VCCAUX (power), G16 VCCAUX (power), H7 VCCAUX (power), H9 VCCIO0 (power), H10 VCCIO0 (power), H11 VCCIO0 (power), H12 VCCIO1 (power), H13 VCCIO1 (power), H14 VCCIO1 (power), H16 VCCAUX (power), J6 VCC (power), J7 VCC (power), J8 VCCIO7 (power), J15 VCCIO2 (power), J16 VCC (power), J17 VCC (power), K6 VCC (power), K7 VCC (power), K8 VCCIO7 (power), K15 VCCIO2 (power), K16 VCC (power), K17 VCC (power), L6 VCC (power), L7 VCCIO7 (power), L8 VCCIO7 (power), L15 VCCIO2 (power), L16 VCCIO2 (power), L17 VCC (power), M6 VCC (power), M7 VCCIO6 (power), M8 VCCIO6 (power), M15 VCCIO3 (power), M16 VCCIO3 (power), M17 VCC (power), N6 VCC (power), N7 VCC (power), N8 VCCIO6 (power), N15 VCCIO3 (power), N16 VCC (power), N17 VCC (power), P6 VCC (power), P7 VCC (power), P8 VCCIO6 (power), P15 VCCIO3 (power), P16 VCC (power), P17 VCC (power), R7 VCCAUX (power), R9 VCCIO5 (power), R10 VCCIO5 (power), R11 VCCIO5 (power), R12 VCCIO4 (power), R13 VCCIO4 (power), R14 VCCIO4 (power), R16 VCCAUX (power), T7 VCCAUX (power), T8 VCCAUX (power), T11 VCCIO5 (power), T12 VCCIO4 (power), T15 VCCAUX (power), T16 VCCAUX (power), U2 VCCJ (power)
part K pins: A1 GND (power), A22 GND (power), AB1 GND (power), AB22 GND (power), H8 GND (power), H15 GND (power), J9 GND (power), J10 GND (power), J11 GND (power), J12 GND (power), J13 GND (power), J14 GND (power), K9 GND (power), K10 GND (power), K11 GND (power), K12 GND (power), K13 GND (power), K14 GND (power), L9 GND (power), L10 GND (power), L11 GND (power), L12 GND (power), L13 GND (power), L14 GND (power), M9 GND (power), M10 GND (power), M11 GND (power), M12 GND (power), M13 GND (power), M14 GND (power), N9 GND (power), N10 GND (power), N11 GND (power), N12 GND (power), N13 GND (power), N14 GND (power), P9 GND (power), P10 GND (power), P11 GND (power), P12 GND (power), P13 GND (power), P14 GND (power), R8 GND (power), R15 GND (power)
part L pins: A2 NC, A20 NC, A21 NC, AA19 NC, AA20 NC, AB2 NC, AB20 NC, B19 NC, B20 NC, C16 NC, C17 NC, C18 NC, C19 NC, D16 NC, D17 NC, D18 NC, E16 NC, E17 NC, F1 NC, F2 NC, F15 NC, F16 NC, F17 NC, G3 NC, G5 NC, G17 NC, G20 NC, G21 NC, H4 NC, H5 NC, H6 NC, H17 NC, H18 NC, H19 NC, H20 NC, J5 NC, J18 NC, J19 NC, N20 NC, P3 NC, P4 NC, P5 NC, P18 NC, P19 NC, P20 NC, R1 NC, R2 NC, R3 NC, R4 NC, R5 NC, R6 NC, R17 NC, R18 NC, R19 NC, R21 NC, R22 NC, T1 NC, T2 NC, T3 NC, T17 NC, T18 NC, T22 NC, U15 NC, U16 NC, U17 NC, U22 NC, V16 NC, V17 NC, W16 NC, W17 NC, W18 NC, Y16 NC, Y17 NC, Y18 NC, Y19 NC

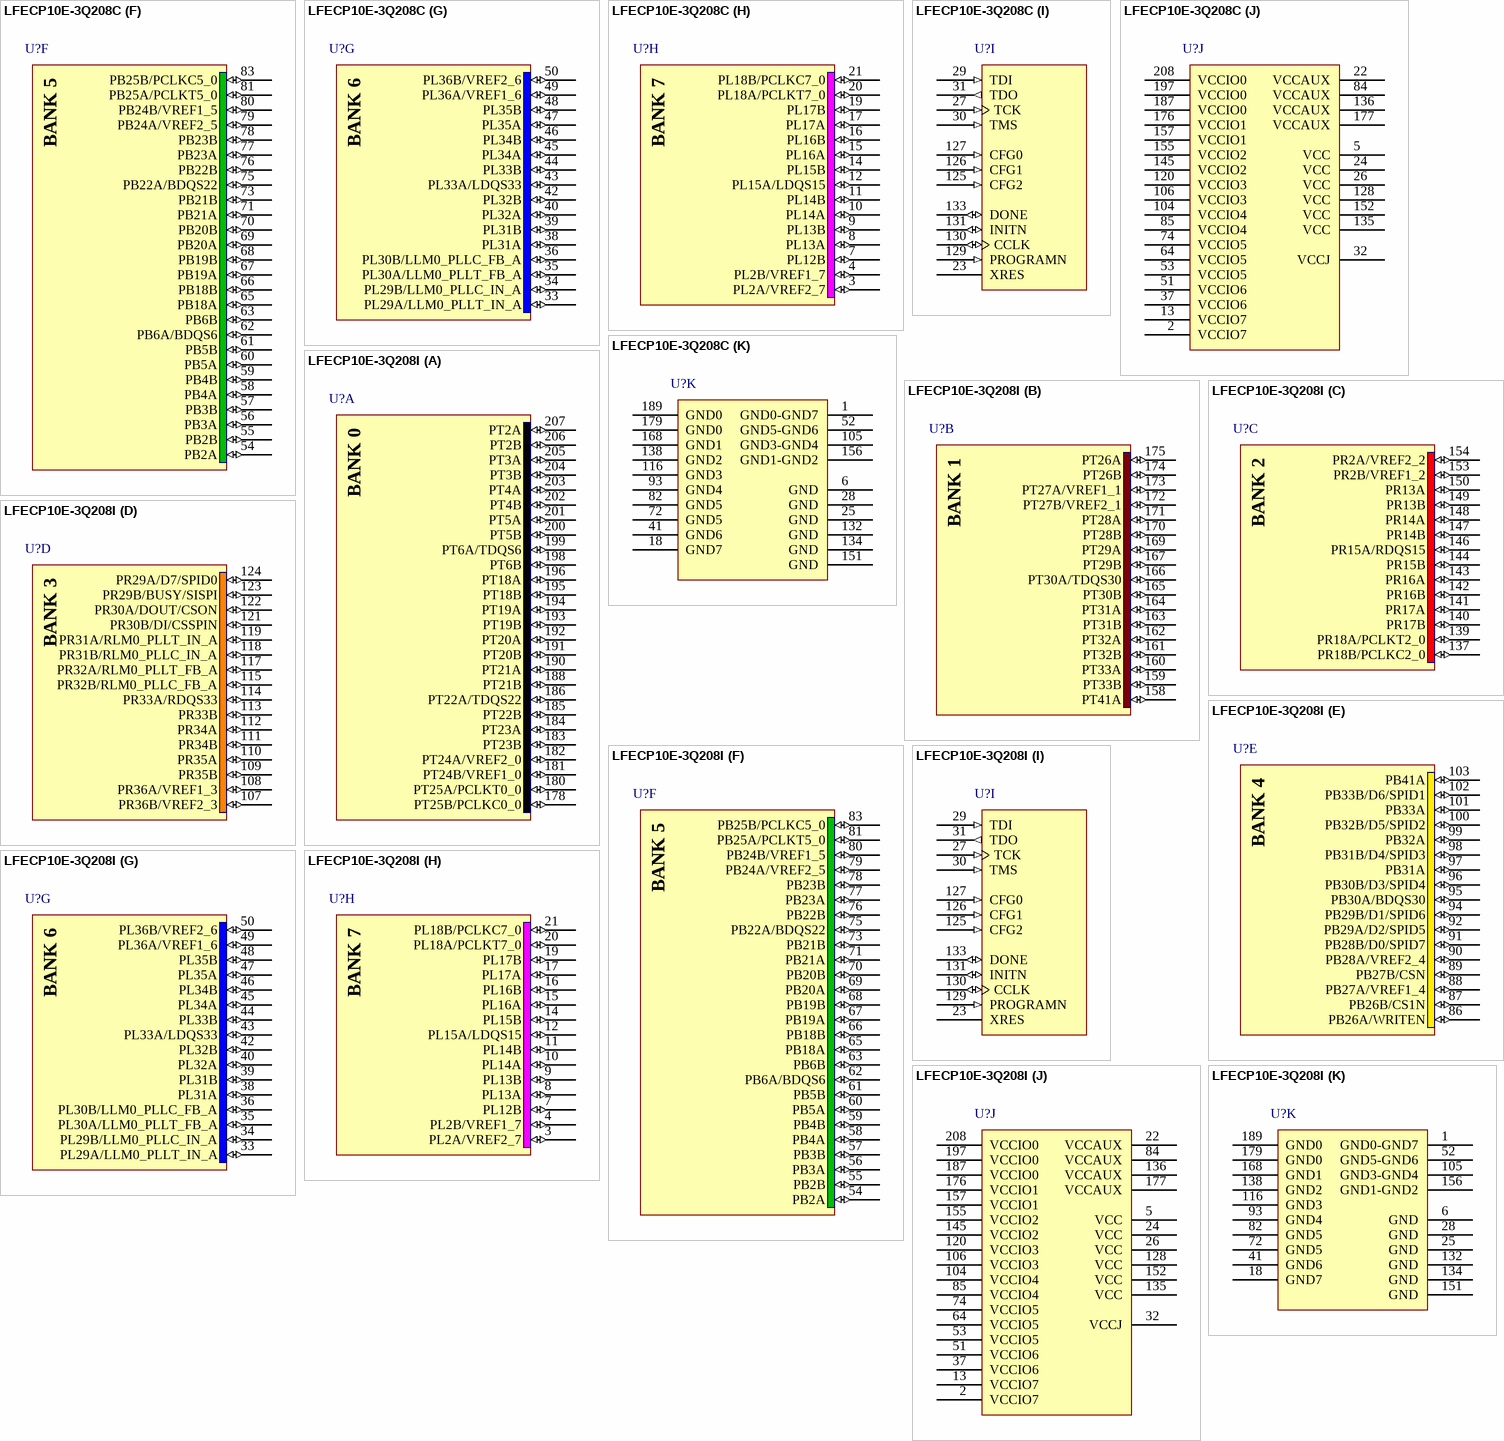
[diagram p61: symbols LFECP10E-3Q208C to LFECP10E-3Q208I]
